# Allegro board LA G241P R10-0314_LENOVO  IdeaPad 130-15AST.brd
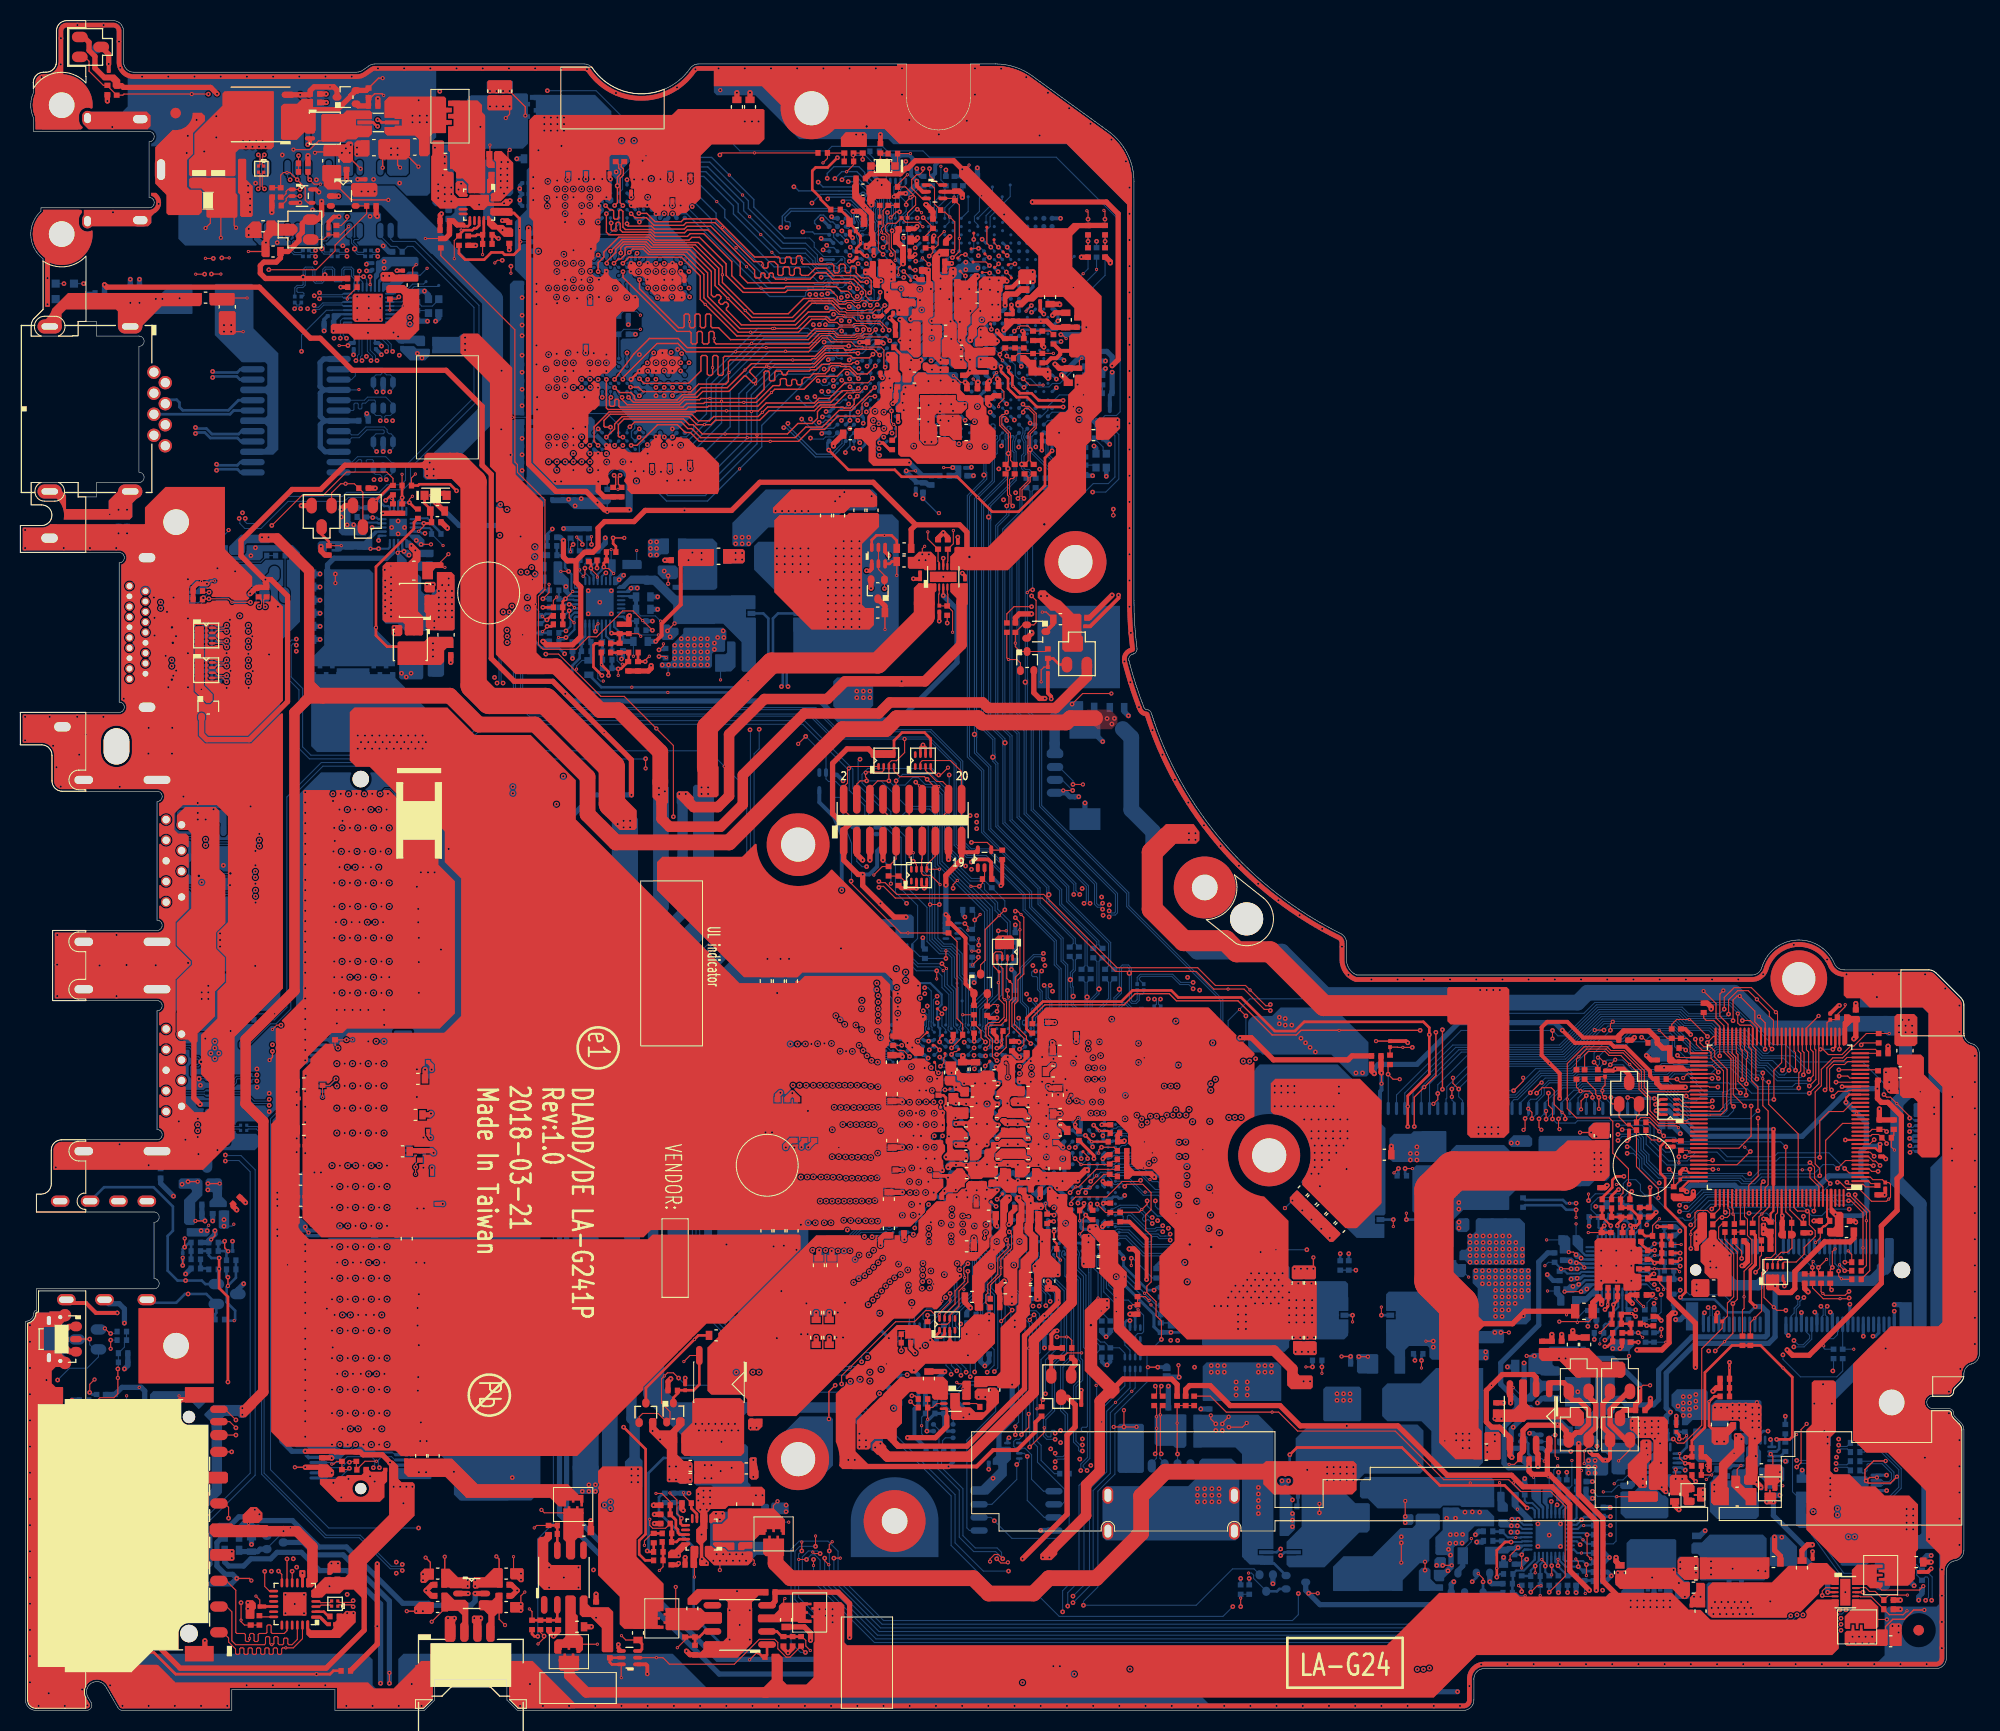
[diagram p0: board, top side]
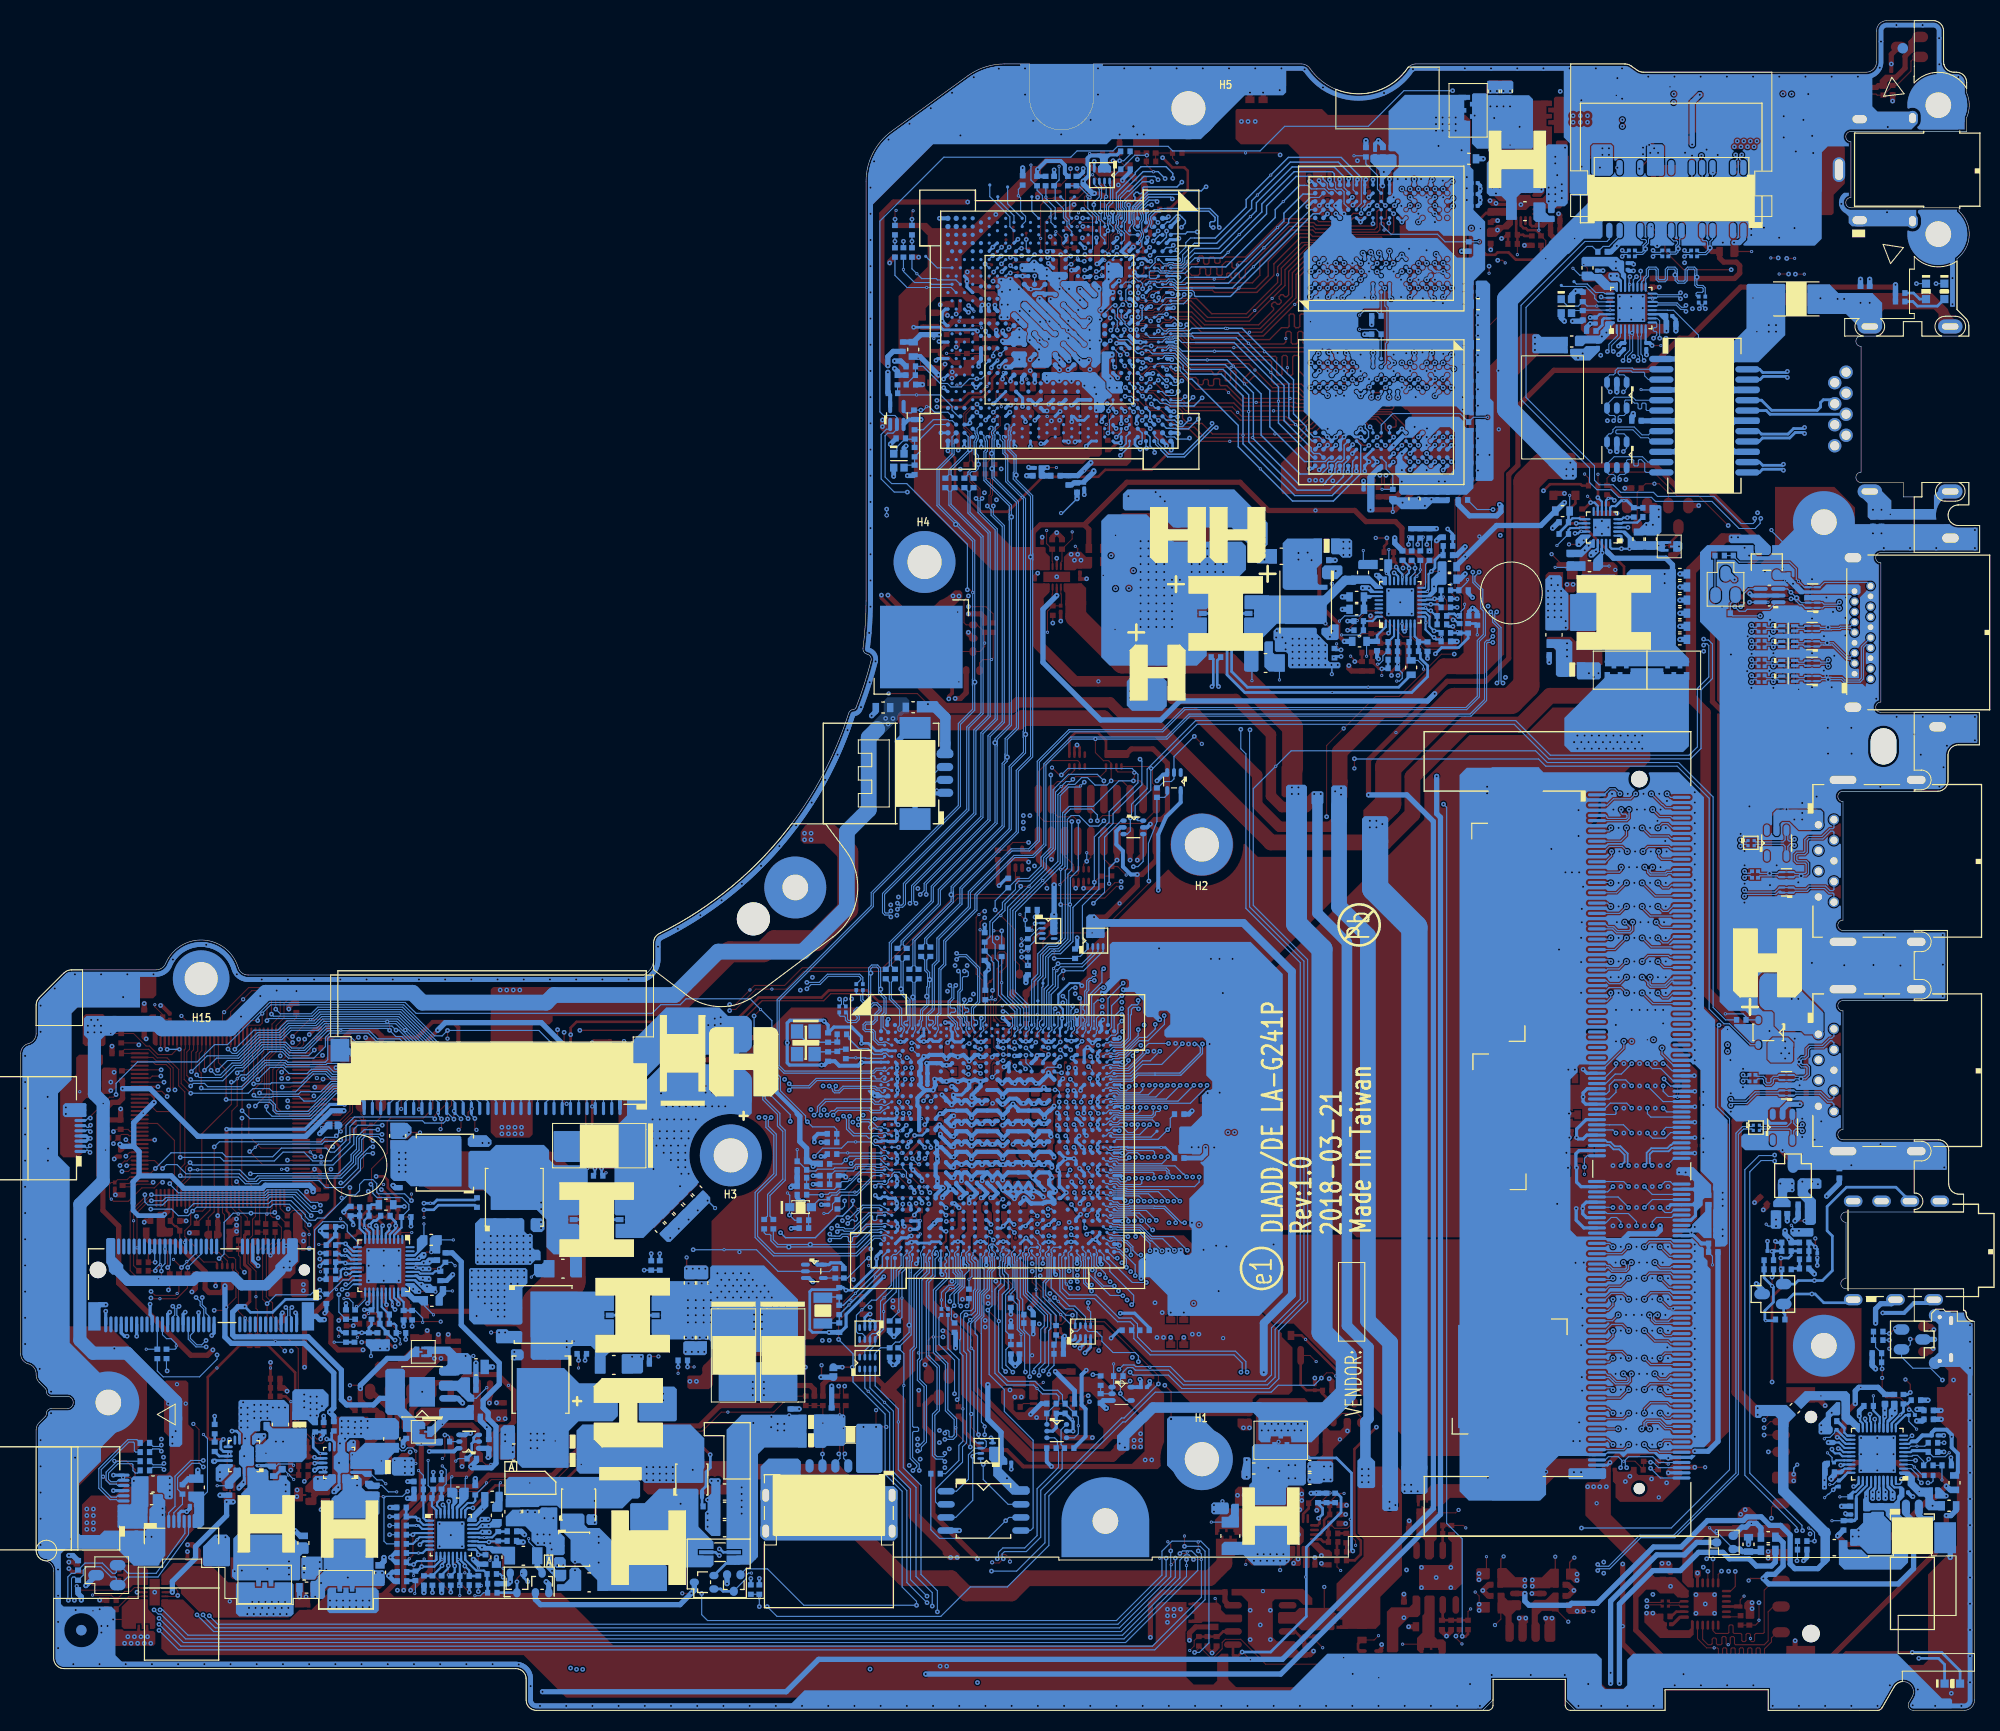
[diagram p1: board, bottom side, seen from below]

Outline 189.87 x 163.86 mm; copper layers: TOP, VCC, IN1, IN2, GND, BOTTOM. Coordinates in mm from the lower left corner of the outline.

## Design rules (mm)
net group 12: nets EXT_MIC_RING2 EXT_MIC_SLEEVE
net group 15: nets DMIC_CLK DMIC_CLK_R
net group CLK_PCIE_LAN: nets CLK_PCIE_LAN CLK_PCIE_LAN#
net group CLK_PCIE_WLAN: nets CLK_PCIE_WLAN CLK_PCIE_WLAN#
net group CLK_PEG_VGA: nets CLK_PEG_VGA CLK_PEG_VGA#
net group CLKREQ: nets VGA_CLKREQ# WLAN_CLKREQ#_R
net group DDR_A_CLK0: nets DDR_A_CLK0 DDR_A_CLK0#
net group DDR_A_CLK1: nets DDR_A_CLK1 DDR_A_CLK1#
net group DDR_A_SDQS0: nets DDR_A_SDQS0 DDR_A_SDQS0#
net group DDR_A_SDQS3: nets DDR_A_SDQS3 DDR_A_SDQS3#
net group DDR_A_SDQS4: nets DDR_A_SDQS4 DDR_A_SDQS4#
net group DDR_A_SDQS5: nets DDR_A_SDQS5 DDR_A_SDQS5#
net group DDR_A_SDQS6: nets DDR_A_SDQS6 DDR_A_SDQS6#
net group DDR_A_SDQS7: nets DDR_A_SDQS7 DDR_A_SDQS7#
net group DDRA_MISC: nets DDR_A_EVENT# DDR_A_RST#
net group EC_SMB_DA1: nets EC_SMB_CK1 EC_SMB_DA1
net group EC_SMB_DA2: nets EC_SMB_CK2 EC_SMB_DA2
net group EC_SMDA: nets EC_SMCA EC_SMDA
net group EDP_AUX: nets EDP_AUXN EDP_AUXP
net group EDP_AUX_C: nets EDP_AUXN_C EDP_AUXP_C
net group EDP_TX0: nets EDP_TXN0 EDP_TXP0
net group EDP_TX0_C: nets EDP_TXN0_C EDP_TXP0_C
net group EDP_TX1: nets EDP_TXN1 EDP_TXP1
net group EDP_TX1_C: nets EDP_TXN1_C EDP_TXP1_C
net group M_CLK0: nets M_CLK0 M_CLK#0
net group M_CLK1: nets M_CLK1 M_CLK#1
net group M_WCKA0_0: nets M_WCKA0_0 M_WCKA0_0#
net group M_WCKA0_1: nets M_WCKA0_1 M_WCKA0_1#
net group M_WCKA1_0: nets M_WCKA1_0 M_WCKA1_0#
net group M_WCKA1_1: nets M_WCKA1_1 M_WCKA1_1#
net group PCIE_ARX_C_GTX_0: nets PCIE_ARX_C_GTX_N0 PCIE_ARX_C_GTX_P0
net group PCIE_ARX_C_GTX_1: nets PCIE_ARX_C_GTX_N1 PCIE_ARX_C_GTX_P1
net group PCIE_ARX_C_GTX_2: nets PCIE_ARX_C_GTX_N2 PCIE_ARX_C_GTX_P2
net group PCIE_ARX_C_GTX_3: nets PCIE_ARX_C_GTX_N3 PCIE_ARX_C_GTX_P3
net group PCIE_ARX_GTX_0: nets PCIE_ARX_GTX_N0 PCIE_ARX_GTX_P0
net group PCIE_ARX_GTX_1: nets PCIE_ARX_GTX_N1 PCIE_ARX_GTX_P1
net group PCIE_ARX_GTX_2: nets PCIE_ARX_GTX_N2 PCIE_ARX_GTX_P2
net group PCIE_ARX_GTX_3: nets PCIE_ARX_GTX_N3 PCIE_ARX_GTX_P3
net group PCIE_ATX_C_GRX_0: nets PCIE_ATX_C_GRX_N0 PCIE_ATX_C_GRX_P0
net group PCIE_ATX_C_GRX_1: nets PCIE_ATX_C_GRX_N1 PCIE_ATX_C_GRX_P1
net group PCIE_ATX_C_GRX_2: nets PCIE_ATX_C_GRX_N2 PCIE_ATX_C_GRX_P2
net group PCIE_ATX_C_GRX_3: nets PCIE_ATX_C_GRX_N3 PCIE_ATX_C_GRX_P3
net group PCIE_ATX_GRX_0: nets PCIE_ATX_GRX_N0 PCIE_ATX_GRX_P0
net group PCIE_ATX_GRX_1: nets PCIE_ATX_GRX_N1 PCIE_ATX_GRX_P1
net group PCIE_ATX_GRX_2: nets PCIE_ATX_GRX_N2 PCIE_ATX_GRX_P2
net group PCIE_ATX_GRX_3: nets PCIE_ATX_GRX_N3 PCIE_ATX_GRX_P3
net group RJ45_RX1: nets RJ45_RX1+ RJ45_RX1-
net group RJ45_TX0: nets RJ45_TX0+ RJ45_TX0-
net group RJ45_TX2: nets RJ45_TX2+ RJ45_TX2-
net group RJ45_TX3: nets RJ45_TX3+ RJ45_TX3-
net group SATA_ARX_C_DTX_0: nets SATA_ARX_C_DTX_N0 SATA_ARX_C_DTX_P0
net group SATA_ARX_DTX_0: nets SATA_ARX_DTX_N0 SATA_ARX_DTX_P0
net group SATA_ARX_DTX_1: nets SATA_ARX_DTX_N1 SATA_ARX_DTX_P1
net group SATA_ATX_C_DRX_0: nets SATA_ATX_C_DRX_N0 SATA_ATX_C_DRX_P0
net group SATA_ATX_DRX_0: nets SATA_ATX_DRX_N0 SATA_ATX_DRX_P0
net group SATA_ATX_DRX_1: nets SATA_ATX_DRX_N1 SATA_ATX_DRX_P1
net group SENSE: nets VCCSENSE_VGA VSSSENSE_VGA
net group USB3_ATX_DRX_1: nets USB3_ATX_DRX_N1 USB3_ATX_DRX_P1
net group USB20_5_R: nets USB20_N5_R USB20_P5_R
net group USB20_6_R: nets USB20_N6_R USB20_P6_R
net group USB20_P1: nets USB20_N1 USB20_P1
net group 10: nets EC_SCI# H_PROCHOT# I2C0_SCL LAN_CLKREQ# PROCHOT# PXS_RST# SUSP SUSP# WLAN_CLKREQ#
net group 28: nets 32K_X1 32K_X2 48M_X1 48M_X1_R 48M_X2 48M_X2_R
net group AUDIO: nets HP_OUTL HP_OUTR HPOUT_L HPOUT_L1 HPOUT_R HPOUT_R1 LINE1-L LINE1-R
net group CLOCK: nets RTC_CLK
net group CPU-SV: nets APU_SVT SVC_RT3661 SVD_RT3661
net group DDRA_CMD: nets DDR_A_CKE0 DDR_A_CKE1 DDR_A_ODT0 DDR_A_ODT1 DDR_A_SACT# DDR_A_SBG0 DDR_A_SBG1 DDR_A_SBS0# DDR_A_SBS1# DDR_A_SCAS# DDR_A_SCS0# DDR_A_SCS1# DDR_A_SMA0 DDR_A_SMA1 DDR_A_SMA2 DDR_A_SMA3 DDR_A_SMA4 DDR_A_SMA5 DDR_A_SMA6 DDR_A_SMA7 DDR_A_SMA8 DDR_A_SMA9 DDR_A_SMA10 DDR_A_SMA11 DDR_A_SMA12 DDR_A_SMA13 DDR_A_SRAS# DDR_A_SWE#
net group DDRA_D0: nets DDR_A_SDM0 DDR_A_SDQ0 DDR_A_SDQ1 DDR_A_SDQ2 DDR_A_SDQ3 DDR_A_SDQ4 DDR_A_SDQ5 DDR_A_SDQ6 DDR_A_SDQ7
net group DDRA_D1: nets DDR_A_SDM1 DDR_A_SDQ8 DDR_A_SDQ9 DDR_A_SDQ10 DDR_A_SDQ11 DDR_A_SDQ12 DDR_A_SDQ13 DDR_A_SDQ14 DDR_A_SDQ15
net group DDRA_D2: nets DDR_A_SDM2 DDR_A_SDQ16 DDR_A_SDQ17 DDR_A_SDQ18 DDR_A_SDQ19 DDR_A_SDQ20 DDR_A_SDQ21 DDR_A_SDQ22 DDR_A_SDQ23
net group DDRA_D3: nets DDR_A_SDM3 DDR_A_SDQ24 DDR_A_SDQ25 DDR_A_SDQ26 DDR_A_SDQ27 DDR_A_SDQ28 DDR_A_SDQ29 DDR_A_SDQ30 DDR_A_SDQ31
net group DDRA_D4: nets DDR_A_SDM4 DDR_A_SDQ32 DDR_A_SDQ33 DDR_A_SDQ34 DDR_A_SDQ35 DDR_A_SDQ36 DDR_A_SDQ37 DDR_A_SDQ38 DDR_A_SDQ39
net group DDRA_D5: nets DDR_A_SDM5 DDR_A_SDQ40 DDR_A_SDQ41 DDR_A_SDQ42 DDR_A_SDQ43 DDR_A_SDQ44 DDR_A_SDQ45 DDR_A_SDQ46 DDR_A_SDQ47
net group DDRA_D6: nets DDR_A_SDM6 DDR_A_SDQ48 DDR_A_SDQ49 DDR_A_SDQ50 DDR_A_SDQ51 DDR_A_SDQ52 DDR_A_SDQ53 DDR_A_SDQ54 DDR_A_SDQ55
net group DDRA_D7: nets DDR_A_SDM7 DDR_A_SDQ56 DDR_A_SDQ57 DDR_A_SDQ58 DDR_A_SDQ59 DDR_A_SDQ60 DDR_A_SDQ61 DDR_A_SDQ62 DDR_A_SDQ63
net group DDRA_DQS: nets DDR_A_SDQS1 DDR_A_SDQS1# DDR_A_SDQS2 DDR_A_SDQS2#
net group DMIC: nets DMIC_DAT
net group GPU-SV: nets GPU_SVC GPU_SVD GPU_SVT
net group HDA: nets HDA_BITCLK HDA_BITCLK_AUDIO HDA_SDIN0 HDA_SDIN0_AUDIO HDA_SDIN1 HDA_SDIN2 HDA_SDOUT HDA_SDOUT_AUDIO HDA_SYNC HDA_SYNC_AUDIO
net group HDMI: nets APU_DP1_AUXN APU_DP1_AUXP APU_DP1_N0 APU_DP1_N1 APU_DP1_N2 APU_DP1_N3 APU_DP1_P0 APU_DP1_P1 APU_DP1_P2 APU_DP1_P3 HDMI_CLKN HDMI_CLKP HDMI_CTRL_CLK HDMI_CTRL_DAT HDMI_L_CLKN HDMI_L_CLKP HDMI_L_TX_N0 HDMI_L_TX_N1 HDMI_L_TX_N2 HDMI_L_TX_P0 HDMI_L_TX_P1 HDMI_L_TX_P2 HDMI_TX_N0 HDMI_TX_N1 HDMI_TX_N2 HDMI_TX_P0 HDMI_TX_P1 HDMI_TX_P2
net group I2C: nets APU_SCLK0 APU_SDATA0 I2C0_SCL_TP I2C0_SDA_TP
net group I2C0_SCL: nets I2C0_SDA
net group KB: nets KSI0 KSI1 KSI2 KSI3 KSI4 KSI5 KSI6 KSI7 KSO0 KSO1 KSO2 KSO3 KSO4 KSO5 KSO6 KSO7 KSO8 KSO9 KSO10 KSO11 KSO12 KSO13 KSO14 KSO15 KSO16 KSO16_R KSO17 KSO17_R
net group LAN: nets LAN_MDIN0 LAN_MDIN1 LAN_MDIN2 LAN_MDIN3 LAN_MDIP0 LAN_MDIP1 LAN_MDIP2 LAN_MDIP3
net group LPC: nets LPC_AD0 LPC_AD1 LPC_AD2 LPC_AD3 LPC_CLK0_EC LPC_CLK1 LPC_CLKRUN# LPC_FRAME# LPC_RST# LPC_RST#_R
net group PCIE-LAN: nets PCIE_ARX_C_DTX_N0 PCIE_ARX_C_DTX_P0 PCIE_ARX_DTX_N0 PCIE_ARX_DTX_P0 PCIE_ATX_C_DRX_N0 PCIE_ATX_C_DRX_P0 PCIE_ATX_DRX_N0 PCIE_ATX_DRX_P0
net group PCIE-WLAN: nets PCIE_ARX_DTX_N2 PCIE_ARX_DTX_P2 PCIE_ATX_C_DRX_N2 PCIE_ATX_C_DRX_P2 PCIE_ATX_DRX_N2 PCIE_ATX_DRX_P2
net group SD: nets SD_CD_N SD_CLK SD_CLK_R SD_CMD SD_D0 SD_D1 SD_D2 SD_D3 SD_WP
net group SMB: nets APU_SIC APU_SID VGA_SMB_CK3 VGA_SMB_DA3
net group SPI: nets APU_SPI_CLK APU_SPI_CLK_R APU_SPI_CS1# APU_SPI_CS2# APU_SPI_HOLD# APU_SPI_MISO APU_SPI_MOSI APU_SPI_WP#
net group SPK: nets SPK_L1- SPK_L1-_CONN SPK_L2+ SPK_L2+_CONN SPK_R1- SPK_R1-_CONN SPK_R2+ SPK_R2+_CONN
net group USB2.0: nets USB20_CR_N3 USB20_CR_P3 USB20_N2 USB20_N2_L USB20_N2_R USB20_N3 USB20_N5 USB20_N6 USB20_P2 USB20_P2_L USB20_P2_R USB20_P3 USB20_P5 USB20_P6
net group USB3.0: nets USB3_ARX_DTX_N1 USB3_ARX_DTX_N2 USB3_ARX_DTX_P1 USB3_ARX_DTX_P2 USB3_ATX_C_DRX_N1 USB3_ATX_C_DRX_N2 USB3_ATX_C_DRX_P1 USB3_ATX_C_DRX_P2 USB3_ATX_DRX_N2 USB3_ATX_DRX_P2
net group VRAM_ADD: nets M0_MA0 M0_MA1 M0_MA2 M0_MA3 M0_MA4 M0_MA5 M0_MA6 M0_MA7 M0_MA8 M1_MA0 M1_MA1 M1_MA2 M1_MA3 M1_MA4 M1_MA5 M1_MA6 M1_MA7 M1_MA8 M_ADBI0 M_ADBI1
net group VRAM_CTL: nets M_CAS#0 M_CAS#1 M_CKE0 M_CKE1 M_CS0B#0 M_CS1B#0 M_RAS#0 M_RAS#1 M_WE#0 M_WE#1
net group VRAM_D0: nets M_DA0 M_DA1 M_DA2 M_DA3 M_DA4 M_DA5 M_DA6 M_DA7 M_DBI0#
net group VRAM_D1: nets M_DA8 M_DA9 M_DA10 M_DA11 M_DA12 M_DA13 M_DA14 M_DA15 M_DBI1#
net group VRAM_D2: nets M_DA16 M_DA17 M_DA18 M_DA19 M_DA20 M_DA21 M_DA22 M_DA23 M_DBI2#
net group VRAM_D3: nets M_DA24 M_DA25 M_DA26 M_DA27 M_DA28 M_DA29 M_DA30 M_DA31 M_DBI3#
net group VRAM_D4: nets M_DA32 M_DA33 M_DA34 M_DA35 M_DA36 M_DA37 M_DA38 M_DA39 M_DBI4#
net group VRAM_D5: nets M_DA40 M_DA41 M_DA42 M_DA43 M_DA44 M_DA45 M_DA46 M_DA47 M_DBI5#
net group VRAM_D6: nets M_DA48 M_DA49 M_DA50 M_DA51 M_DA52 M_DA53 M_DA54 M_DA55 M_DBI6#
net group VRAM_D7: nets M_DA56 M_DA57 M_DA58 M_DA59 M_DA60 M_DA61 M_DA62 M_DA63 M_DBI7#
net group VRAM_EDC: nets M_EDC_0 M_EDC_1 M_EDC_2 M_EDC_3 M_EDC_4 M_EDC_5 M_EDC_6 M_EDC_7
nets with their own width: min track width 0.254; nets +EC_VCCA ECAGND
nets with their own width: min track width 0.381; nets +RTC_BATT +RTCBATT_R
nets with their own width: min track width 0.508; nets +0.6VS +0.95VALW +0.95VS +1.2V +1.8VALW +1.8VGS +1.8VS +1.35VS_VRAM +3VALW +3VALW_EC +3VGS +3VL +3VS +3VS_CMOS +5VALW +5VS +19V_P1 +CHGRTC_R +FBA_VREFC0 +RTCBATT +VDDR3 +VGA_CORE +VL ASGATE_CHG_R GND GNDA N17215363 N22801431
nets with their own width: min track width 1.016; nets +3V_LAN +3VS_WLAN +CARD_3V3 HGNDA HGNDB
nets with their own width: min track width 1.524; nets +LCDVDD +LCDVDD_CONN
nets with their own width: min track width 2.032; nets +5V_HDD +5V_ODD
nets with their own width: min track width 2.54; nets +LEDVDD

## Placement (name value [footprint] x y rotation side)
C179  100P_0402_50V8J  [C_0402]  169.64 47.35 270 top
C180  0.1U_0201_10V6K  [C_0201]  160.94 50.49 270 top
C181  0.1U_0201_10V6K  [C_0201]  180.24 54.3 270 top
C182  1000P_0402_50V7K  [C_0402]  177.89 67.01 90 top
C183  1000P_0402_50V7K  [C_0402]  176.35 47.46 0 top
C184  0.1U_0201_10V6K  [C_0201]  160.75 62.93 270 top
C187  0.1U_0201_10V6K  [C_0201]  175.41 67.57 270 top
C189  100P_0402_50V8J  [C_0402]  163.15 67.67 90 top
C190  100P_0402_50V8J  [C_0402]  168.75 45.57 0 top
C191  47P_0402_50V8J  [C_0402]  166.14 45.51 0 top
C193  0.1U_0201_10V6K  [C_0201]  160.87 51.49 90 top
C201  4.7U_0402_6.3V6M  [C_0402]  31.59 150.35 270 top
C202  0.1U_0201_10V K X5R  [C_0201]  23.75 142.97 180 top
C203  10U_0603_6.3V6M  [C_0603]  24.22 143.92 180 top
C204  0.1U_0201_10V K X5R  [C_0201]  29.85 143.12 90 top
C205  4.7U_0805_25V6-K  [C_0805]  35.09 151.54 180 top
C206  0.1U_0201_10V K X5R  [C_0201]  27.94 141 180 bottom
C207  0.1U_0201_10V K X5R  [C_0201]  27.94 141.57 180 bottom
C208  0.1U_0201_10V K X5R  [C_0201]  30.74 141 180 bottom
C209  0.1U_0201_10V K X5R  [C_0201]  30.74 141.57 180 bottom
C210  0.1U_0201_10V K X5R  [C_0201]  33.98 141 180 bottom
C211  0.1U_0201_10V K X5R  [C_0201]  33.98 141.57 180 bottom
C216  10P_0402_50V8J  [C_0402]  36.07 141.44 0 bottom
C217  1U_0201_6.3V6M  [C_0201]  33.43 147.88 90 top
C232  0.1U_0201_10V K X5R  [C_0201]  177.8 18.64 180 bottom
C233  0.01U_0402_16V7K  [C_0402]  177.37 23.27 0 bottom
C234  0.01U_0402_16V7K  [C_0402]  177.37 24.16 0 bottom
C235  0.01U_0402_16V7K  [C_0402]  177.37 25.05 0 bottom
C236  0.01U_0402_16V7K  [C_0402]  177.37 25.94 0 bottom
C237  1000P_0402_50V7K  [C_0402]  177.84 19.4 180 bottom
C238  10U_0603_6.3V6M  [C_0603]  177.88 20.48 180 bottom
C239  0.1U_0201_10V K X5R  [C_0201]  178.65 17.85 270 bottom
C243  4.7U_0402_6.3V6M  [C_0402]  164.04 46.22 180 top
C244  0.1U_0201_10V K X5R  [C_0201]  163.06 44.81 180 top
C271  0.1U_0201_10V K X5R  [C_0201]  132.74 64.32 90 top
C272  0.1U_0201_10V K X5R  [C_0201]  155.91 56.8 270 top
C275  0.1U_0201_10V K X5R  [C_0201]  153.58 61.45 90 top
C280  0.1U_0201_10V K X5R  [C_0201]  172.89 19.84 0 bottom
C281  82P_0402_50V8G  [C_0402]  184.3 12.62 270 bottom
C282  82P_0402_50V8G  [C_0402]  184.3 13.61 90 bottom
C301  0.1U_0201_10V K X5R  [C_0201]  22.29 61 180 bottom
C302  0.1U_0201_10V K X5R  [C_0201]  22.29 61.63 180 bottom
C303  470P_0402_50V7K  [C_0402]  17.93 87.08 90 bottom
C304  220U_6.3V_M  [C_MP6VLPS220MC4R2]  20.54 69.68 270 bottom
C305  0.1U_0201_10V K X5R  [C_0201]  18.23 64.55 180 bottom
C371  10U_0603_6.3V6M  [C_0603]  106.97 97.25 180 bottom
C823  4.7U_0402_6.3V6M  [C_0402]  175.36 47.46 180 top
C831  22P_0402_50V8J  [C_0402]  181.57 56.34 90 top
C832  0.1U_0201_10V6K  [C_0201]  160.24 55.25 270 top
C833  100P_0402_50V8J  [C_0402]  180.18 56.34 90 top
C834  100P_0402_50V8J  [C_0402]  180.1 63.72 0 top
C835  100P_0402_50V8J  [C_0402]  164.04 47.13 180 top
C836  1000P_0402_50V7K  [C_0402]  179.99 50.91 270 top
C837  100P_0402_50V8J  [C_0402]  171.68 47.27 180 top
C838  100P_0402_50V8J  [C_0402]  172.81 46.31 90 top
C839  0.1U_0201_10V K X5R  [C_0201]  22.04 80.74 180 bottom
C840  0.1U_0201_10V K X5R  [C_0201]  22.04 81.37 180 bottom
C843  0.1U_0201_10V K X5R  [C_0201]  173.71 14.11 90 top
C844  10U_0603_6.3V6M  [C_0603]  172.67 13.12 90 top
C845  10U_0603_6.3V6M  [C_0603]  183.03 14.38 0 top
C846  0.1U_0201_10V K X5R  [C_0201]  183.44 13.43 0 top
C847  2200P_0402_25V7K  [C_0402]  180.61 10.7 0 top
C848  1000P_0402_50V7K  [C_0402]  180.61 9.81 0 top
C849  0.1U_0201_10V K X5R  [C_0201]  161.95 9.58 90 top
C850  10U_0603_6.3V6M  [C_0603]  162.84 8.92 90 top
C851  10U_0603_6.3V6M  [C_0603]  180.56 6.7 0 top
C852  0.1U_0201_10V K X5R  [C_0201]  180.77 7.59 0 top
C853  4.7U_0402_6.3V6M  [C_0402]  63.39 26.19 0 top
C854  4.7U_0402_6.3V6M  [C_0402]  71.59 28.02 90 top
C855  1U_0201_6.3V6M  [C_0201]  70.83 28.71 270 top
C856  4.7U_0603_6.3V6M  [C_0603]  88.04 31.46 90 top
C857  10U_0603_6.3V6M  [C_0603]  94.39 31.78 270 top
C858  1U_0201_6.3V6M  [C_0201]  93.44 31.56 270 top
C859  0.1U_0201_10V6K  [C_0201]  64.42 31.04 90 top
C860  330P_0402_50V7K  [C_0402]  92.98 29.43 0 top
C861  1U_0201_6.3V6M  [C_0201]  89.78 28.48 0 top
C2147  0.1U_0201_10V K X5R  [C_0201]  182.44 59.97 180 top
C2148  1000P_0402_50V7K  [C_0402]  182.67 60.74 180 top
C2149  10U_0603_6.3V6M  [C_0603]  182.91 61.88 180 top
C2150  100P_0402_50V8J  [C_0402]  89.49 29.75 0 bottom
C2151  100P_0402_50V8J  [C_0402]  88.62 29.75 180 bottom
C2152  0.1U_0201_10V K X5R  [C_0201]  8.54 158.39 90 top
C2153  10P_0402_50V8J  [C_0402]  8.41 157.59 270 top
C2154  0.1U_0201_10V6K  [C_0201]  180.75 51.19 270 top
C2155  0.1U_0201_10V K X5R  [C_0201]  164.35 37.72 0 top
CA1  4.7U_0402_6.3V6M  [C_0402]  9.55 18.94 90 bottom
CA40  4.7U_0402_6.3V6M  [C_0402]  14.96 23.08 180 bottom
CA43  100P_0402_50V8J  [C_0402]  9.48 34.64 0 bottom
CA44  1U_0201_6.3V6M  [C_0201]  4.7 20.79 180 bottom
CA45  1000P_0402_50V7K  [C_0402]  41.06 11.1 180 top
CA46  1U_0201_6.3V6M  [C_0201]  19.95 44.54 0 bottom
CA47  1000P_0402_50V7K  [C_0402]  46.43 12.18 0 top
CA48  0.1U_0201_10V K X5R  [C_0201]  4.62 26.66 180 bottom
CA49  0.1U_0201_10V K X5R  [C_0201]  7.5 21.14 180 bottom
CA50  470P_0402_50V7K  [C_0402]  18.62 49.09 270 bottom
CA51  2.2U_0402_6.3V6M  [C_0402]  4.04 25.06 0 bottom
CA52  22P_0402_50V8J  [C_0402]  3.62 23.76 180 bottom
CA53  0.1U_0201_10V K X5R  [C_0201]  10.85 19.51 270 bottom
CA54  1U_0201_6.3V6M  [C_0201]  15.71 44.33 270 bottom
CA55  0.1U_0201_10V K X5R  [C_0201]  13.13 28.92 0 bottom
CA56  220P_0402_50V7K  [C_0402]  19.95 42.77 0 bottom
CA57  1U_0201_6.3V6M  [C_0201]  13.62 21.71 90 bottom
CA58  1U_0201_6.3V6M  [C_0201]  13.13 29.68 0 bottom
CA59  220P_0402_50V7K  [C_0402]  16.53 42.85 0 bottom
CA60  1U_0201_6.3V6M  [C_0201]  12.41 18.41 90 bottom
CA61  2.2U_0402_6.3V6M  [C_0402]  14.74 28.05 180 bottom
CA62  0.1U_0201_10V K X5R  [C_0201]  4.7 21.43 180 bottom
CA63  2.2U_0402_6.3V6M  [C_0402]  10.27 29.52 0 bottom
CA64  2.2U_0402_6.3V6M  [C_0402]  12.51 19.79 90 bottom
CA65  470P_0402_50V7K  [C_0402]  16.65 49.05 0 bottom
CA66  4.7U_0402_6.3V6M  [C_0402]  12.16 16.24 270 bottom
CA67  1000P_0402_50V7K  [C_0402]  41.06 12.18 180 top
CA68  1U_0201_6.3V6M  [C_0201]  13.83 27.21 0 bottom
CA69  0.1U_0201_10V K X5R  [C_0201]  6.84 28.63 180 bottom
CA70  1U_0201_6.3V6M  [C_0201]  14.09 24.03 0 bottom
CA71  1000P_0402_50V7K  [C_0402]  46.43 11.1 0 top
CC1  0.1U_0201_10V6K  [C_0201]  109.88 67.68 90 bottom
CC2  0.1U_0201_10V6K  [C_0201]  110.52 67.68 90 bottom
CC3  0.1U_0201_10V6K  [C_0201]  108.23 69.84 90 bottom
CC4  0.1U_0201_10V6K  [C_0201]  108.87 69.84 90 bottom
CC7  0.01U_0402_16V7K  [C_0402]  85.09 80.9 270 top
CC8  0.1U_0201_10V6K  [C_0201]  111.57 49.04 90 bottom
CC9  150P_0402_50V8J  [C_0402]  85.18 30.71 270 bottom
CC10  0.1U_0201_10V6K  [C_0201]  81.28 31.34 180 bottom
CC11  12P_0402_50V8J  [C_0402]  110.52 37.57 270 bottom
CC12  12P_0402_50V8J  [C_0402]  110.52 40.09 90 bottom
CC13  150P_0402_50V8J  [C_0402]  89.7 35.46 180 bottom
CC14  0.1U_0201_10V6K  [C_0201]  94.43 24.03 180 bottom
CC15  6.8P_0402_50V8C  [C_0402]  111.6 64.79 90 bottom
CC16  6.8P_0402_50V8C  [C_0402]  111.6 63.86 270 bottom
CC18  0.22U_0402_6.3V6K  [C_0402]  100.98 34.19 0 top
CC19  1U_0201_6.3V6M  [C_0201]  102.22 29.62 0 top
CC20  22U_0603_6.3V6M  [C_0603]  84.46 62.14 90 top
CC21  22U_0603_6.3V6M  [C_0603]  84.46 60.49 270 top
CC22  22U_0603_6.3V6M  [C_0603]  84.48 55.97 270 top
CC23  22U_0603_6.3V6M  [C_0603]  84.17 48.86 90 top
CC24  22U_0603_6.3V6M  [C_0603]  84.17 47.46 270 top
CC25  22U_0603_6.3V6M  [C_0603]  72.29 47.21 270 top
CC26  22U_0603_6.3V6M  [C_0603]  73.56 47.21 270 top
CC27  22U_0603_6.3V6M  [C_0603]  74.83 47.21 270 top
CC28  22U_0603_6.3V6M  [C_0603]  72.23 70.01 90 top
CC29  22U_0603_6.3V6M  [C_0603]  73.5 70.01 90 top
CC30  22U_0603_6.3V6M  [C_0603]  74.77 70.01 90 top
CC31  0.22U_0402_6.3V6K  [C_0402]  87.06 62.89 90 top
CC32  0.22U_0402_6.3V6K  [C_0402]  75.28 58.31 90 top
CC33  0.22U_0402_6.3V6K  [C_0402]  75.02 56.18 270 top
CC34  0.22U_0402_6.3V6K  [C_0402]  75.97 56.18 270 top
CC35  0.22U_0402_6.3V6K  [C_0402]  73.37 58.31 90 top
CC36  0.22U_0402_6.3V6K  [C_0402]  74.32 58.31 90 top
CC37  180P_0402_50V8J  [C_0402]  76.93 56.18 270 top
CC38  0.22U_0402_6.3V6K  [C_0402]  88.97 60.57 270 top
CC39  0.22U_0402_6.3V6K  [C_0402]  89.16 54.76 0 top
CC40  0.22U_0402_6.3V6K  [C_0402]  88.75 52.82 270 top
CC41  0.22U_0402_6.3V6K  [C_0402]  89.17 50.97 0 top
CC42  180P_0402_50V8J  [C_0402]  84.8 53.32 270 top
CC43  180P_0402_50V8J  [C_0402]  85.63 47.22 270 top
CC44  10U_0603_6.3V6M  [C_0603]  92.93 40.1 180 top
CC45  22U_0603_6.3V6M  [C_0603]  97.18 41.94 0 top
CC46  10U_0603_6.3V6M  [C_0603]  97.18 40.67 0 top
CC47  0.22U_0402_6.3V6K  [C_0402]  97.68 46.77 0 top
CC48  1U_0201_6.3V6M  [C_0201]  97.97 48.23 0 top
CC49  1U_0201_6.3V6M  [C_0201]  97.97 47.59 0 top
CC50  1U_0201_6.3V6M  [C_0201]  96.92 50.46 180 top
CC51  10U_0603_6.3V6M  [C_0603]  96.17 40.92 180 top
CC52  0.22U_0402_6.3V6K  [C_0402]  96.88 47.78 180 top
CC53  10U_0603_6.3V6M  [C_0603]  99.72 40.92 90 top
CC54  0.22U_0402_6.3V6K  [C_0402]  98.85 50.51 180 top
CC55  10U_0603_6.3V6M  [C_0603]  105.18 43.4 180 top
CC56  10U_0603_6.3V6M  [C_0603]  105.18 44.61 180 top
CC57  0.22U_0402_6.3V6K  [C_0402]  105.63 46.31 90 top
CC58  10U_0603_6.3V6M  [C_0603]  78.39 36.86 270 top
CC59  10U_0603_6.3V6M  [C_0603]  77.12 36.86 270 top
CC60  10U_0603_6.3V6M  [C_0603]  78.39 39.27 270 top
CC61  1U_0201_6.3V6M  [C_0201]  89.92 49.69 180 top
CC62  10U_0603_6.3V6M  [C_0603]  78.64 42.45 90 top
CC63  0.22U_0402_6.3V6K  [C_0402]  91.71 49.05 0 top
CC64  10U_0603_6.3V6M  [C_0603]  77.12 39.27 270 top
CC65  10U_0603_6.3V6M  [C_0603]  77.37 42.45 90 top
CC66  10U_0603_6.3V6M  [C_0603]  91 45 0 top
CC67  10U_0603_6.3V6M  [C_0603]  93.12 47.97 0 top
CC68  0.22U_0402_6.3V6K  [C_0402]  92.15 51.03 180 top
CC69  180P_0402_50V8J  [C_0402]  93.17 51.06 0 top
CC70  10U_0603_6.3V6M  [C_0603]  100.9 46.23 180 top
CC71  0.22U_0402_6.3V6K  [C_0402]  101.16 49.75 90 top
CC72  0.22U_0402_6.3V6K  [C_0402]  99.6 65.8 90 top
CC73  0.22U_0402_6.3V6K  [C_0402]  101.42 65.5 0 top
CC74  0.22U_0402_6.3V6K  [C_0402]  96.1 63.96 90 top
CC75  0.22U_0402_6.3V6K  [C_0402]  105.63 57.7 270 top
CC76  0.22U_0402_6.3V6K  [C_0402]  95.46 48.73 0 top
CC104  0.22U_0402_6.3V6K  [C_0402]  106.01 70.95 90 bottom
CC105  0.22U_0402_6.3V6K  [C_0402]  105.12 70.95 90 bottom
CC106  0.22U_0402_6.3V6K  [C_0402]  104.87 72.98 90 bottom
CC107  0.22U_0402_6.3V6K  [C_0402]  103.98 72.98 90 bottom
CC108  0.22U_0402_6.3V6K  [C_0402]  103.72 70.95 90 bottom
CC109  0.22U_0402_6.3V6K  [C_0402]  102.83 70.95 90 bottom
CC110  0.22U_0402_6.3V6K  [C_0402]  102.58 73.11 90 bottom
CC111  0.22U_0402_6.3V6K  [C_0402]  101.69 73.11 90 bottom
CC112  100P_0402_50V8J  [C_0402]  84.58 65.39 270 top
CC113  100P_0402_50V8J  [C_0402]  87.66 73.83 270 bottom
CC114  100P_0402_50V8J  [C_0402]  96.42 72.73 90 bottom
CC115  100P_0402_50V8J  [C_0402]  90.4 65.51 0 top
CC129  4.7U_0402_6.3V6M  [C_0402]  143.03 29.82 270 top
CC130  4.7U_0402_6.3V6M  [C_0402]  157.46 29.11 180 top
CC131  4.7U_0402_6.3V6M  [C_0402]  147.47 35.79 270 top
CC132  22U_0603_6.3V6M  [C_0603]  151.67 34.76 90 top
CC133  22U_0603_6.3V6M  [C_0603]  150.46 34.76 90 top
CC134  4.7U_0402_6.3V6M  [C_0402]  149.38 35.79 270 top
CC135  4.7U_0402_6.3V6M  [C_0402]  148.43 35.79 270 top
CC162  100P_0402_50V8J  [C_0402]  114.59 50.83 180 bottom
CD201  0.1U_0201_10V6K  [C_0201]  35.36 23.33 0 top
CD202  2.2U_0402_6.3V6M  [C_0402]  35.26 22.51 0 top
CD203  10U_0603_6.3V6M  [C_0603]  40.03 23.97 90 top
CD204  10U_0603_6.3V6M  [C_0603]  38.83 23.97 90 top
CD205  1U_0201_6.3V6M  [C_0201]  37.94 24.25 90 top
CD206  0.1U_0201_10V6K  [C_0201]  37.37 24.25 90 top
CD207  4.7U_0402_6.3V6M  [C_0402]  29.21 23.58 90 top
CD208  0.1U_0201_10V6K  [C_0201]  29.21 22.8 270 top
CD210  0.1U_0201_10V6K  [C_0201]  25.61 45.99 0 bottom
CD211  1000P_0402_50V7K  [C_0402]  25.38 47.32 0 bottom
CD212  0.1U_0201_10V6K  [C_0201]  25.64 50.64 0 bottom
CD213  0.1U_0201_10V6K  [C_0201]  25.61 46.56 0 bottom
CD214  10U_0603_6.3V6M  [C_0603]  27.84 51.47 180 top
CD215  10U_0603_6.3V6M  [C_0603]  27.84 48.35 180 top
CD216  10U_0603_6.3V6M  [C_0603]  37.8 61.24 0 top
CD217  10U_0603_6.3V6M  [C_0603]  37.56 57.75 0 top
CD218  10U_0603_6.3V6M  [C_0603]  36.32 54.21 0 top
CD219  10U_0603_6.3V6M  [C_0603]  37.43 46.45 270 top
CD220  10U_0603_6.3V6M  [C_0603]  28.16 60.8 180 top
CD221  10U_0603_6.3V6M  [C_0603]  28.16 56.29 180 top
CD222  1U_0201_6.3V6M  [C_0201]  27.5 54.77 180 top
CD223  1U_0201_6.3V6M  [C_0201]  27.56 59.34 180 top
CD224  1U_0201_6.3V6M  [C_0201]  36.48 46.04 270 top
CD225  1U_0201_6.3V6M  [C_0201]  38.91 62.88 0 top
CD226  1U_0201_6.3V6M  [C_0201]  38.91 56.21 0 top
CD227  1U_0201_6.3V6M  [C_0201]  39.3 52.04 0 top
CD228  1U_0201_6.3V6M  [C_0201]  27.5 49.81 180 top
CD229  1U_0201_6.3V6M  [C_0201]  39.74 49.12 0 top
CD230  330U_D3_2.5VY_R6M  [C_D3]  38.62 89.5 270 top
CD231  100P_0402_50V8J  [C_0402]  30.48 65.03 90 top
CH11  0.1U_0201_10V K X5R  [C_0201]  18.51 110.16 90 bottom
CH12  0.1U_0201_10V K X5R  [C_0201]  21.58 112.74 0 bottom
CH13  0.1U_0201_10V K X5R  [C_0201]  21.4 104.61 180 bottom
CH14  0.1U_0201_10V K X5R  [C_0201]  21.4 105.25 180 bottom
CH15  0.1U_0201_10V K X5R  [C_0201]  21.4 99.73 180 bottom
CH16  0.1U_0201_10V K X5R  [C_0201]  21.4 100.36 180 bottom
CH17  0.1U_0201_10V K X5R  [C_0201]  21.4 103.09 180 bottom
CH18  0.1U_0201_10V K X5R  [C_0201]  21.4 103.73 180 bottom
CH19  0.1U_0201_10V K X5R  [C_0201]  21.4 101.25 180 bottom
CH20  0.1U_0201_10V K X5R  [C_0201]  21.4 101.88 180 bottom
CL1  1U_0201_6.3V6M  [C_0201]  39.49 131.79 0 bottom
CL2  0.1U_0201_10V K X5R  [C_0201]  30.36 135.22 180 bottom
CL3  0.1U_0201_10V K X5R  [C_0201]  36.98 132.72 270 bottom
CL4  0.1U_0201_10V K X5R  [C_0201]  34.43 132.59 270 bottom
CL5  0.1U_0201_10V K X5R  [C_0201]  32.29 132.59 270 bottom
CL6  0.1U_0201_10V K X5R  [C_0201]  34.67 139.71 180 bottom
CL7  0.1U_0201_10V K X5R  [C_0201]  37.18 135.07 270 bottom
CL8  1U_0201_6.3V6M  [C_0201]  34.67 140.34 180 bottom
CL10  0.1U_0201_10V K X5R  [C_0201]  37.09 139.03 90 top
CL11  0.1U_0201_10V K X5R  [C_0201]  27.21 137.1 270 bottom
CL12  0.1U_0201_10V K X5R  [C_0201]  26.57 137.1 270 bottom
CL13  27P_0402_50V8J  [C_0402]  38.45 137.52 270 bottom
CL14  27P_0402_50V8J  [C_0402]  38.45 134.83 90 bottom
CL15  0.1U_0201_10V K X5R  [C_0201]  37.09 139.03 90 bottom
CL18  0.01U_0402_16V7K  [C_0402]  33.7 125.06 180 bottom
CL19  1000P_0603_50V8J  [C_0603]  18.63 137 180 top
CL20  4.7U_0402_6.3V6M  [C_0402]  30.33 134.46 180 bottom
CL21  4.7U_0402_6.3V6M  [C_0402]  37.81 132.89 270 bottom
CLRP1  SHORT PADS  [SHORTPADS]  111.09 32.8 270 bottom
CR1  0.1U_0201_10V K X5R  [C_0201]  29.94 12.76 90 top
CR2  4.7U_0402_6.3V6M  [C_0402]  30.7 12.72 90 top
CR3  5P_0402_50V8C  [C_0402]  22.3 8.27 90 top
CR4  1U_0201_6.3V6M  [C_0201]  22.6 10.06 0 top
CR5  1U_0201_6.3V6M  [C_0201]  30.48 8.35 180 top
CR6  4.7U_0402_6.3V6M  [C_0402]  21.95 17.62 90 top
CR7  0.1U_0201_10V K X5R  [C_0201]  22.84 17.79 90 top
CV1  0.22U_0402_6.3V6K  [C_0402]  100.23 119.49 270 bottom
CV2  0.22U_0402_6.3V6K  [C_0402]  99.34 119.49 270 bottom
CV3  0.22U_0402_6.3V6K  [C_0402]  98.39 119.49 270 bottom
CV4  0.22U_0402_6.3V6K  [C_0402]  97.5 119.49 270 bottom
CV5  0.22U_0402_6.3V6K  [C_0402]  97.31 120.82 270 top
CV6  0.22U_0402_6.3V6K  [C_0402]  98.2 120.82 270 top
CV7  0.22U_0402_6.3V6K  [C_0402]  96.36 120.82 270 top
CV8  0.22U_0402_6.3V6K  [C_0402]  95.47 120.82 270 top
CV11  0.082U_0402_16V  [C_0402]  98.14 133.75 270 top
CV15  0.68U_0402_10V  [C_0402]  103.13 130.33 0 bottom
CV17  15P_0402_50V8J  [C_0402]  103.22 120.76 270 bottom
CV18  15P_0402_50V8J  [C_0402]  104.09 123.35 0 bottom
CV19  10U_0603_6.3V6M  [C_0603]  101.32 134.13 90 top
CV20  1U_0201_6.3V6M  [C_0201]  96.17 134.8 90 top
CV21  0.1U_0201_10V6K  [C_0201]  95.53 134.8 90 top
CV26  1U_0201_6.3V6M  [C_0201]  98.83 137.23 270 top
CV27  10U_0603_6.3V6M  [C_0603]  99.79 137.76 270 top
CV28  0.68U_0402_10V  [C_0402]  96.25 131.13 0 top
CV29  0.68U_0402_10V  [C_0402]  95.44 132.12 90 top
CV30  10U_0603_6.3V6M  [C_0603]  97.33 137.77 90 top
CV31  0.1U_0201_10V7K  [C_0201]  90.85 113.23 270 top
CV32  0.1U_0201_10V7K  [C_0201]  87.19 110.34 90 top
CV33  1U_0201_6.3V6M  [C_0201]  95.6 137.41 90 top
CV36  4.7U_0402_6.3V6M  [C_0402]  102.44 105.95 0 top
CV37  1U_0201_6.3V6M  [C_0201]  102.61 105.12 0 top
CV38  10U_0603_6.3V6M  [C_0603]  103.28 123.66 0 top
CV39  0.1U_0201_10V6K  [C_0201]  99.57 123.73 180 top
CV40  2.2U_0402_6.3V6M  [C_0402]  83.49 140.25 180 top
CV41  2.2U_0402_6.3V6M  [C_0402]  83.49 139.34 180 top
CV42  2.2U_0402_6.3V6M  [C_0402]  84.67 131.22 0 top
CV43  10U_0603_6.3V6M  [C_0603]  81.13 123.75 180 top
CV44  10U_0603_6.3V6M  [C_0603]  69.43 154.78 90 top
CV45  10U_0603_6.3V6M  [C_0603]  70.7 154.78 90 top
CV46  1U_0201_6.3V6M  [C_0201]  99.57 123.09 180 top
CV47  2.2U_0402_6.3V6M  [C_0402]  84.67 130.32 0 top
CV48  2.2U_0402_6.3V6M  [C_0402]  86.46 136.43 90 top
CV49  0.1U_0201_10V6K  [C_0201]  85.66 136.74 90 top
CV50  0.1U_0201_10V6K  [C_0201]  83.66 138.12 180 top
CV51  0.1U_0201_10V6K  [C_0201]  84.58 136.11 270 top
CV52  0.1U_0201_10V6K  [C_0201]  83.93 135.68 225 top
CV53  0.1U_0201_10V6K  [C_0201]  83.94 129.74 180 top
CV54  10U_0603_6.3V6M  [C_0603]  87.35 129.24 180 top
CV55  10U_0603_6.3V6M  [C_0603]  86.39 125.76 0 top
CV56  1U_0201_6.3V6M  [C_0201]  85.05 126.12 270 top
CV57  1U_0201_6.3V6M  [C_0201]  86.79 127.35 0 top
CV58  1U_0201_6.3V6M  [C_0201]  88.36 127.96 270 top
CV59  1U_0201_6.3V6M  [C_0201]  89.75 127.96 270 top
CV60  1U_0201_6.3V6M  [C_0201]  86.79 126.71 0 top
CV61  10U_0603_6.3V6M  [C_0603]  101.55 130.14 270 top
CV62  1U_0201_6.3V6M  [C_0201]  93.63 130.37 270 top
CV63  0.1U_0201_10V6K  [C_0201]  92.99 130.37 270 top
CV64  1U_0201_6.3V6M  [C_0201]  93.5 132.53 270 top
CV65  1U_0201_6.3V6M  [C_0201]  94.13 132.53 270 top
CV66  1U_0201_6.3V6M  [C_0201]  92.86 132.53 270 top
CV80  1U_0201_6.3V6M  [C_0201]  89.7 130.1 90 top
CV81  10U_0603_6.3V6M  [C_0603]  84.89 142.59 0 top
CV82  1U_0201_6.3V6M  [C_0201]  85.59 141.57 0 top
CV83  0.1U_0201_10V7K  [C_0201]  99.57 101.17 270 top
CV84  10U_0603_6.3V6M  [C_0603]  80.93 147.48 0 top
CV85  1U_0201_6.3V6M  [C_0201]  81.65 146.52 0 top
CV86  0.1U_0201_10V6K  [C_0201]  82.68 142.21 270 top
CV90  0.1U_0201_10V K X5R  [C_0201]  88.42 142.44 270 top
CV91  10U_0603_6.3V6M  [C_0603]  80.36 144.3 0 top
CV92  1U_0201_6.3V6M  [C_0201]  80.97 143.41 180 top
CV93  0.1U_0201_10V6K  [C_0201]  81.02 141.45 270 top
CV94  1U_0201_6.3V6M  [C_0201]  90.99 120.49 0 bottom
CV95  1U_0201_6.3V6M  [C_0201]  86.77 119.07 270 bottom
CV96  120P_0402_50V8J  [C_0402]  79.85 151.02 90 top
CV97  68P_0402_50V8J  [C_0402]  81.63 151.02 90 top
CV98  0.1U_0201_10V K X5R  [C_0201]  83.28 144.85 270 top
CV99  0.1U_0201_10V K X5R  [C_0201]  85.97 144.72 180 top
CV120  1U_0201_6.3V6M  [C_0201]  89.05 127.96 270 top
CV121  1U_0201_6.3V6M  [C_0201]  90.45 127.96 270 top
CV122  10U_0603_6.3V6M  [C_0603]  89.69 124.05 180 top
CV123  10U_0603_6.3V6M  [C_0603]  103.34 132.68 270 bottom
CV124  0.1U_0201_10V6K  [C_0201]  85.59 140.94 0 top
CV160  10U_0603_6.3V6M  [C_0603]  54.76 118.2 270 bottom
CV161  1U_0201_6.3V6M  [C_0201]  49.22 127.35 180 bottom
CV162  1U_0201_6.3V6M  [C_0201]  49.22 121 180 bottom
CV163  1U_0201_6.3V6M  [C_0201]  52.54 118.05 270 bottom
CV164  1U_0201_6.3V6M  [C_0201]  60.63 120.68 0 top
CV165  0.1U_0201_10V K X5R  [C_0201]  49.22 125.76 180 bottom
CV166  0.1U_0201_10V K X5R  [C_0201]  49.22 119.41 180 bottom
CV167  0.1U_0201_10V K X5R  [C_0201]  51.53 118.05 270 bottom
CV168  10U_0603_6.3V6M  [C_0603]  49.3 136.36 180 bottom
CV169  1U_0201_6.3V6M  [C_0201]  52.5 149 0 top
CV170  1U_0201_6.3V6M  [C_0201]  56.5 149.06 0 top
CV171  1U_0201_6.3V6M  [C_0201]  62.41 149 0 top
CV172  1U_0201_6.3V6M  [C_0201]  49.22 137.57 180 bottom
CV173  0.1U_0201_10V K X5R  [C_0201]  59.76 147.29 180 top
CV174  0.01U_0402_16V7K  [C_0402]  85.77 135.57 0 top
CV175  0.01U_0402_16V7K  [C_0402]  83.95 127.47 0 top
CV176  0.01U_0402_16V7K  [C_0402]  84.99 129.25 270 top
CV177  0.01U_0402_16V7K  [C_0402]  83.04 132.68 180 top
CV178  0.01U_0402_16V7K  [C_0402]  84.71 137.27 90 top
CV179  0.01U_0402_16V7K  [C_0402]  103.52 124.74 0 top
CV181  1U_0201_6.3V6M  [C_0201]  87.63 130.33 180 top
CV187  0.1U_0201_10V K X5R  [C_0201]  49.22 148.11 180 bottom
CV188  0.1U_0201_10V K X5R  [C_0201]  64.35 148.84 0 top
CV271  2200P_0402_50V7K  [C_0402]  89.88 112.6 90 top
CV281  2200P_0402_50V7K  [C_0402]  88.93 112.6 90 top
CV291  1U_0201_6.3V6M  [C_0201]  87.18 109.11 90 top
CV301  1U_0201_6.3V6M  [C_0201]  91.54 109.09 90 top
CV373  10U_0603_6.3V6M  [C_0603]  49.3 132.43 180 bottom
CV374  0.1U_0201_10V K X5R  [C_0201]  49.22 130.52 180 bottom
CV375  0.1U_0201_10V K X5R  [C_0201]  49.22 128.94 180 bottom
CV376  0.1U_0201_10V K X5R  [C_0201]  49.22 124.17 180 bottom
CV377  0.1U_0201_10V K X5R  [C_0201]  49.22 122.59 180 bottom
CV378  0.1U_0201_10V K X5R  [C_0201]  53.69 118.05 270 bottom
CV379  0.1U_0201_10V K X5R  [C_0201]  64.32 121 0 top
CV380  0.1U_0201_10V K X5R  [C_0201]  62.35 120.68 0 top
CV381  10U_0603_6.3V6M  [C_0603]  50.19 150.46 180 bottom
CV382  0.1U_0201_10V K X5R  [C_0201]  62.6 146.46 0 top
CV383  0.1U_0201_10V K X5R  [C_0201]  54.22 149.06 0 top
CV384  0.1U_0201_10V K X5R  [C_0201]  49.22 138.4 180 bottom
CV385  0.1U_0201_10V K X5R  [C_0201]  63.76 138.61 0 top
CV386  0.1U_0201_10V K X5R  [C_0201]  49.22 147.03 180 bottom
CV387  0.1U_0201_10V K X5R  [C_0201]  49.22 145.89 180 bottom
CV388  0.1U_0201_10V K X5R  [C_0201]  54.63 136.49 0 top
CV389  1U_0201_6.3V6M  [C_0201]  55.37 132.24 180 top
CV391  1U_0201_6.3V6M  [C_0201]  58.57 150.74 90 bottom
CV392  1U_0201_6.3V6M  [C_0201]  59.11 118.39 0 bottom
CV1380  0.1U_0201_10V K X5R  [C_0201]  89.05 107.13 270 top
D1  -  [L03ESDL5V0CC3-2_SOT23-3]  5.46 35.97 90 bottom
D281  -  [PSOT24C_SOT23-3]  182.55 13.11 270 bottom
D301  L05ESDL5V0NA-4 SLP2510P8 ESD  [YSCLAMP0524P_SLP2510P8-10-9]  18.26 59.62 90 bottom
D302  L30ESDL5V0C6-4 SOT23 ESD  [AZC099-04SPR7G_SOT23-6]  20.03 55.3 180 bottom
D303  L03ESDL5V0CC3-2  [L03ESDL5V0CC3-2_SOT23-3]  155.92 60.89 180 top
D304  L05ESDL5V0NA-4 SLP2510P8 ESD  [YSCLAMP0524P_SLP2510P8-10-9]  18.26 79.29 90 bottom
D305  L30ESDL5V0C6-4 SOT23 ESD  [AZC099-04SPR7G_SOT23-6]  20.6 82.85 180 bottom
DA3  AZC099-04S.R7G_SOT23-6  [AZC099-04SPR7G_SOT23-6]  42.47 12.28 270 top
DA8  -  [L03ESDL5V0CC3-2_SOT23-3]  21.05 40.37 270 bottom
DA9  -  [L03ESDL5V0CC3-2_SOT23-3]  18.06 52.89 0 bottom
DC3  RB751V-40 SOD-323  [RB751V-40TE17_SOD323-2]  115.31 48.8 90 bottom
DH1  L05ESDL5V0NA-4 SLP2510P8 ESD  [YSCLAMP0524P_SLP2510P8-10-9]  15.72 106.92 90 bottom
DH2  L05ESDL5V0NA-4 SLP2510P8 ESD  [YSCLAMP0524P_SLP2510P8-10-9]  15.78 103.17 90 bottom
DH3  L05ESDL5V0NA-4 SLP2510P8 ESD  [YSCLAMP0524P_SLP2510P8-10-9]  15.78 99.8 90 bottom
DL1  AZC099-04S.R7G_SOT23-6  [AZC099-04SPR7G_SOT23-6]  34.19 128.79 0 bottom
DL2  AZC099-04S.R7G_SOT23-6  [AZC099-04SPR7G_SOT23-6]  34.19 123.01 0 bottom
DL3  -  [BS4200N-C-LV_SMB-F2]  15.53 136.87 0 bottom
DV1  RB751V_SOD323  [CH751H-40PT_SOD323-2]  84.76 149.76 180 top
FD1  CF  [FIDUCIAL_C40M80]  183.99 7.78 0 top
FD2  CF  [FIDUCIAL_C40M80]  15.03 154.89 0 top
FD3  CF  [FIDUCIAL_C40M80]  7.42 161.18 180 bottom
FD4  CF  [FIDUCIAL_C40M80]  183.99 7.78 180 bottom
H1  HOLEA  [H_3P3]  75.37 24.36 270 top
H2  HOLEA  [H_3P3]  75.37 83.96 270 top
H3  HOLEA  [H_3P3]  121.03 53.82 270 top
H4  HOLEA  [H_3P3]  102.25 111.36 270 top
H5  HOLEA  [H_3P3]  76.67 155.36 270 top
H6  HOLEA  [H_2P5]  3.98 155.66 270 top
H7  HOLEA  [H_2P5]  3.98 143.16 270 top
H8  HOLEA  [H_2P5]  15.07 115.23 0 top
H9  HOLEA  [H_2P5]  15.07 35.36 270 top
H10  HOLEA  [H_2P5]  84.72 18.36 270 top
H11  HOLEA  [H_3P2N]  118.84 76.75 0 top
H12  HOLEA  [H_2P5]  181.37 29.86 270 top
H13  HOLEA  [H_2P5]  114.78 79.8 270 top
H14  HOLEA  [H_3P5X2P5N]  9.29 93.48 90 top
H15  HOLEA  [H_3P2]  172.37 70.96 0 top
J1  SHORT PADS  [SHORTPADS]  171.22 46.13 0 top
J2  SHORT PADS  [SHORTPADS]  159.54 56.74 180 bottom
J4  -  [JUMP_43X79]  180.85 13.11 180 top
J5  -  [JUMP_43X79]  178.02 7.55 90 top
JBAT1  SUYIN_125022HB008M200ZL  [SUYIN_125022HB008M200ZL_8P-T]  107.14 23.71 180 bottom
JDCIN1  SINGA_2DC3169-000111F  [SINGA_2DC3169-000111F_5P-T]  13.61 149.41 270 bottom
JDIMM1  DEREN_40-42271-26001RHF  [DEREN_40-42271-26001RHF_260P-T]  37.07 89.29 270 bottom
JEDP1  ACES_87242-3001-09  [ACES_87242-3001-09_30P]  22.87 143.51 0 bottom
JFAN1  ACES_50271-0040N-001  [ACES_50271-0040N-001_4P]  100.27 88.98 270 bottom
JHDD1  ACES_51530-01001-P01  [ACES_51530-01001-P01_10P]  179.88 18.31 270 bottom
JHDMI1  ACON_HMRA4-AK120C  [ACON_HMRA4-AK120C_19P]  10.55 100.03 90 bottom
JHDT1  SAMTE_ASP-136446-07-B  [SAMTE_ASP-136446-07-B_20P-T]  79.78 84.29 0 top
JHP1  SINGA_2SJ3095-140111F  [SINGA_2SJ3095-140111F_6P-T]  12.23 39.83 270 bottom
JKB1  JXT_FP257H-032S10M  [JXT_FP257H-032S10M_32P]  131.77 58.37 0 bottom
JLAN1  PS_601012-008041  [PS_601012-008041_8P]  12.92 129.77 270 top
JODD2  ACES_51530-01001-P01  [ACES_51530-01001-P01_10P]  184.08 54.2 270 bottom
JRTC1  ACES_50271-0020N-001  [ACES_50271-0020N-001_2P]  7.12 19.64 180 bottom
JSD1  DEREN_43-42095-01111RHF-R  [DEREN_43-42095-01111RHF-R_11P]  19.22 10.07 270 top
JSPK1  ACES_50278-00401-001  [ACES_50278-00401-001_4P]  41.77 7.63 0 top
JTP1  ACES_51522-00601-001  [ACES_51522-00601-001_6P]  175.52 18.32 180 bottom
JUSB1  ACON_TARAN-9R1391  [ACON_TARAN-9R1391_9P]  15.6 65.58 90 bottom
JUSB2  ACON_TARAN-9R1391  [ACON_TARAN-9R1391_9P]  15.6 85.88 90 bottom
JWLAN1  LOTES_APCI0128-P005A  [LOTES_APCI0128-P005A_75P]  163.12 37.43 0 bottom
L20  BLM15AX601SN1D_0402_2P  [MURAT_BLM15AX300SN1D_2P]  155.77 64.99 180 top
L21  BLM15AX601SN1D_0402_2P  [MURAT_BLM15AX300SN1D_2P]  158.65 63.07 270 top
L301  DLM0NSN900HY2D_4P  [MURAT_DLM0NSN900HY2D_4P]  21.92 56.74 180 bottom
L305  DLM0NSN900HY2D_4P  [MURAT_DLM0NSN900HY2D_4P]  22.43 84.35 180 bottom
L307  DLM0NSN900HY2D_4P  [MURAT_DLM0NSN900HY2D_4P]  23.56 149.76 270 top
L308  DLM0NSN900HY2D_4P  [MURAT_DLM0NSN900HY2D_4P]  30.74 10.11 180 top
LA5  0_0603_5%  [R0603_0OHM]  47.78 13.26 180 top
LA6  0_0603_5%  [R0603_0OHM]  47.78 10.03 180 top
LA7  0_0603_5%  [R0603_0OHM]  39.72 13.26 0 top
LA8  0_0603_5%  [R0603_0OHM]  39.72 10.03 0 top
LA9  BLM15PX221SN1D_2P  [MURAT_BLM15PX221SN1D_2P]  4.49 22.78 0 bottom
LED2  LTW-C193TS5-C_WHITE  [LED_LTW-C193TS5-C_2P]  3.37 2.6 180 bottom
LED3  LTW-C193TS5-C_WHITE  [LED_LTW-C193TS5-C_2P]  3.39 138.35 270 bottom
LED4  LTST-C191KFKT-2CA_ORANGE  [LED_LTST-C191KFKT-2CA_2P]  5.17 138.35 270 bottom
LH1  HCM1012GH900BP_4P  [INPAQ_HCM1012GH900BP_4P]  19.16 105.18 180 bottom
LH2  HCM1012GH900BP_4P  [INPAQ_HCM1012GH900BP_4P]  19.16 100.3 180 bottom
LH3  HCM1012GH900BP_4P  [INPAQ_HCM1012GH900BP_4P]  19.16 103.66 180 bottom
LH4  HCM1012GH900BP_4P  [INPAQ_HCM1012GH900BP_4P]  19.16 101.81 180 bottom
LV2  0_0402_5%  [R0402_0OHM]  102.39 135.04 270 top
LV3  0_0402_5%  [R0402_0OHM]  102.63 129.24 90 top
LV4  0_0402_5%  [R0402_0OHM]  104.36 131.78 90 bottom
LV6  0_0402_5%  [R0402_0OHM]  86.05 143.67 180 top
LV7  0_0402_5%  [R0402_0OHM]  81.89 148.56 180 top
LV8  0_0402_5%  [R0402_0OHM]  78.54 145.54 0 top
NOREF  -  []  2.37 35.36 90 top
NOREF#2  -  []  45.34 30.41 90 top
NOREF#3  -  []  76.67 155.36 0 top
NOREF#4  -  []  88.97 156.36 0 top
NOREF#5  -  []  121.03 53.82 90 top
NOREF#6  -  []  102.25 111.36 270 top
NOREF#7  -  []  3.98 155.66 90 top
NOREF#8  -  []  66.1 80.43 270 top
NOREF#9  -  []  84.72 18.36 90 top
NOREF#10  -  []  75.37 83.96 0 top
NOREF#11  -  []  123.8 3.47 0 top
NOREF#12  -  []  75.37 24.36 90 top
NOREF#13  -  []  181.37 29.86 270 top
NOREF#14  -  []  114.78 79.8 270 top
NOREF#15  -  []  107.47 159.86 0 top
NOREF#16  -  []  15.07 115.23 180 top
NOREF#17  -  []  74.96 -30.77 0 top
NOREF#18  -  []  3.98 143.16 90 top
NOREF#19  -  []  63.77 37.86 90 top
NOREF#20  -  []  10.12 144.62 0 top
NOREF#21  -  []  172.37 70.96 0 top
NOREF#22  -  []  63.63 41.69 90 bottom
NOREF#23  -  []  15.07 35.36 270 bottom
NOREF#24  -  []  181.37 29.86 90 bottom
NOREF#25  -  []  46.62 75.46 90 bottom
NOREF#26  -  []  45.41 39.84 90 bottom
NOREF#27  -  []  46.52 57.08 90 bottom
NOREF#28  -  []  45.53 32.38 180 bottom
NOREF#29  -  []  84.72 18.36 90 bottom
NOREF#30  -  []  102.57 103.12 180 bottom
PC101  1000P_0402_50V7K  [C_0402]  20.7 145.39 0 top
PC102  100P_0402_50V8J  [C_0402]  20.7 146.35 0 top
PC103  100P_0402_50V8J  [C_0402]  20.54 150.09 0 top
PC104  1000P_0402_50V7K  [C_0402]  20.54 149.14 0 top
PC201  1000P_0402_50V7K  [C_0402]  111.25 28.41 90 bottom
PC202  0.01U_0402_25V7K  [C_0402]  115.24 28.31 90 bottom
PC401  0.1U_0402_25V7K  [C_0402]  155.37 21.82 270 bottom
PC402  1000P_0402_50V7K  [C_0402]  162 23.72 0 top
PC403  0.1U_0402_25V6  [C_0402]  156.11 25.61 90 bottom
PC404  2200P_0402_50V7K  [C_0402]  155.22 25.61 90 bottom
PC405  10U_0805_25V6K  [C_0805]  153.89 25.47 90 bottom
PC407  22U_0603_6.3V6M  [C_0603]  155.03 12.67 90 top
PC408  22U_0603_6.3V6M  [C_0603]  155.03 12.67 90 bottom
PC409  22U_0603_6.3V6M  [C_0603]  161.44 11.9 0 top
PC410  22U_0603_6.3V6M  [C_0603]  161.44 11.9 0 bottom
PC411  4.7U_0603_6.3V6M  [C_0603]  160.33 21.66 270 top
PC412  680P_0402_50V7K  [C_0402]  158.27 20.73 90 top
PC413  1000P_0402_50V7K  [C_0402]  171.06 25.1 90 bottom
PC414  10U_0805_25V6K  [C_0805]  164.68 26.87 90 bottom
PC415  10U_0805_25V6K  [C_0805]  164.68 26.87 90 top
PC416  2200P_0402_50V7K  [C_0402]  166 27.65 0 bottom
PC417  0.1U_0402_25V6  [C_0402]  166 27.65 0 top
PC418  0.1U_0402_25V7K  [C_0402]  164.49 23.42 270 bottom
PC419  2.2U_0402_6.3V6M  [C_0402]  169.65 21.79 270 bottom
PC420  22U_0603_6.3V6M  [C_0603]  162.46 15.52 90 bottom
PC421  22U_0603_6.3V6M  [C_0603]  163.1 13.17 180 bottom
PC422  22U_0603_6.3V6M  [C_0603]  163.1 14.38 180 bottom
PC423  22U_0603_6.3V6M  [C_0603]  163.1 13.17 180 top
PC424  22U_0603_6.3V6M  [C_0603]  163.1 14.38 180 top
PC425  22U_0603_6.3V6M  [C_0603]  169.19 14.38 0 top
PC426  680P_0402_50V7K  [C_0402]  166.4 22.32 0 top
PC427  4.7U_0603_6.3V6M  [C_0603]  169.45 23.39 180 top
PC428  4.7U_0402_6.3V6M  [C_0402]  162 25.43 0 top
PC429  1U_0201_6.3V6M  [C_0201]  160.49 27.01 90 top
PC451  1000P_0402_50V7K  [C_0402]  165.65 32.16 180 top
PC501  0.1U_0402_25V6  [C_0402]  40.78 102.33 0 bottom
PC502  2200P_0402_50V7K  [C_0402]  40.78 102.33 0 top
PC503  10U_0805_25V6K  [C_0805]  41.24 103.45 90 bottom
PC504  10U_0805_25V6K  [C_0805]  41.24 103.45 90 top
PC505  0.1U_0402_25V7K  [C_0402]  39.59 111.17 90 bottom
PC506  10U_0603_6.3V6M  [C_0603]  31.84 112.87 90 bottom
PC507  10U_0603_6.3V6M  [C_0603]  33.05 112.87 90 bottom
PC508  1U_0402_10V6K  [C_0402]  40.74 115.22 180 top
PC509  22U_0603_6.3V6M  [C_0603]  29.75 103.85 180 bottom
PC510  22U_0603_6.3V6M  [C_0603]  29.75 105.12 180 bottom
PC511  22U_0603_6.3V6M  [C_0603]  29.75 107.66 180 bottom
PC512  22U_0603_6.3V6M  [C_0603]  29.75 106.39 180 bottom
PC513  22U_0603_6.3V6M  [C_0603]  29.75 108.93 180 bottom
PC514  22U_0603_6.3V6M  [C_0603]  29.75 110.2 180 bottom
PC515  0.033U_0402_16V7K  [C_0402]  32.62 115.73 180 bottom
PC516  1U_0402_10V6K  [C_0402]  39.83 115.22 0 bottom
PC517  680P_0402_50V7K  [C_0402]  40.67 111.04 270 top
PC518  0.1U_0402_10V7K  [C_0402]  36.98 117 270 top
PC519  0.1U_0402_10V7K  [C_0402]  36.1 117 270 top
PC601  0.1U_0402_25V6  [C_0402]  64.1 20.15 90 bottom
PC602  680P_0402_50V7K  [C_0402]  72.1 19.59 0 bottom
PC603  0.1U_0402_25V7K  [C_0402]  70.64 16.06 270 top
PC604  2200P_0402_50V7K  [C_0402]  68.86 19.19 90 top
PC605  0.1U_0402_25V6  [C_0402]  71.53 19.19 90 top
PC606  10U_0805_25V6K  [C_0805]  70.2 19.14 90 top
PC608  330P_0402_50V7K  [C_0402]  61.37 16.25 90 top
PC609  22U_0603_6.3V6M  [C_0603]  65.62 22.45 180 bottom
PC610  22U_0603_6.3V6M  [C_0603]  65.62 23.72 180 bottom
PC611  22U_0603_6.3V6M  [C_0603]  65.62 22.45 180 top
PC612  22U_0603_6.3V6M  [C_0603]  65.62 23.72 180 top
PC613  2.2U_0402_6.3V6M  [C_0402]  65.32 14.13 180 top
PC614  1U_0402_6.3V6K  [C_0402]  63.08 15.03 270 top
PC705  2200P_0402_25V7K  [C_0402]  138.18 20.31 270 bottom
PC708  0.1U_0402_25V6  [C_0402]  146.38 13.04 0 bottom
PC715  2200P_0402_50V7K  [C_0402]  150.83 20.57 0 bottom
PC721  0.22U_0603_25V7K  [C_0603]  143.7 19.61 270 bottom
PC747  0.1U_0402_25V6  [C_0402]  150 20.58 180 bottom
PC748  0.1U_0402_25V6  [C_0402]  160.94 65.17 90 top
PC750  0.22U_0603_25V7K  [C_0603]  146.78 21.13 0 bottom
PC751  560P_0402_50V7K  [C_0402]  152.45 13.42 0 bottom
PC752  0.015U_0402_25V7K  [C_0402]  152.45 12.53 0 bottom
PC757  1U_0603_25V6K  [C_0603]  143.75 14.14 90 bottom
PC760  10U_0805_25V6K  [C_0805]  142.14 20.11 270 bottom
PC761  10U_0805_25V6K  [C_0805]  120.78 21.18 0 bottom
PC762  10U_0805_25V6K  [C_0805]  140.41 20.13 270 bottom
PC765  0.1U_0402_25V7K  [C_0402]  139.09 20.31 270 bottom
PC767  680P_0402_50V7K  [C_0402]  137.44 11.9 90 bottom
PC768  1U_0402_16V6K  [C_0402]  142.71 16.44 180 bottom
PC769  1U_0402_16V6K  [C_0402]  142.7 17.37 180 bottom
PC775  10U_0805_25V6K  [C_0805]  120.78 19.4 0 bottom
PC776  10U_0805_25V6K  [C_0805]  120.78 17.62 0 bottom
PC779  0.1U_0402_25V7K  [C_0402]  123.71 19.78 0 bottom
PC801  2.2U_0402_10V6M  [C_0402]  149.19 42.59 270 bottom
PC802  10U_0805_25V6K  [C_0805]  153.32 54.87 90 bottom
PC803  10U_0805_25V6K  [C_0805]  153.32 54.87 90 top
PC804  0.1U_0402_25V7K  [C_0402]  149.52 44.58 270 bottom
PC805  0.47U_0402_25V6K  [C_0402]  156.1 47.97 0 bottom
PC806  680P_0402_50V7K  [C_0402]  139.79 43.01 90 bottom
PC807  0.1U_0402_25V6  [C_0402]  157.89 47.96 90 bottom
PC808  0.1U_0402_25V6  [C_0402]  152.94 40.09 90 top
PC809  82P_0402_50V8J  [C_0402]  153.88 40.16 0 top
PC810  330P_0402_50V8J  [C_0402]  154.26 37.5 0 top
PC811  1000P_0402_25V8J  [C_0402]  152.75 37.86 90 bottom
PC812  330P_0402_50V8J  [C_0402]  155.16 48.75 270 top
PC813  82P_0402_50V8J  [C_0402]  154.22 48.67 180 top
PC814  0.1U_0402_25V6  [C_0402]  156.1 37.5 0 top
PC815  0.1U_0402_25V6  [C_0402]  154.32 35.78 0 top
PC816  0.1U_0402_25V6  [C_0402]  155.79 40.09 90 top
PC817  0.1U_0402_25V6  [C_0402]  157.83 48.75 270 top
PC818  0.1U_0402_25V6  [C_0402]  154.97 47.96 180 bottom
PC819  10P_0402_50V8J  [C_0402]  158.33 37.93 90 bottom
PC822  2.2U_0402_10V6M  [C_0402]  157.71 41.88 180 top
PC823  10U_0805_25V6K  [C_0805]  141.23 25.05 0 bottom
PC824  10U_0805_25V6K  [C_0805]  141.23 25.05 0 top
PC825  0.1U_0402_25V7K  [C_0402]  148.91 40.81 0 bottom
PC826  0.47U_0402_25V6K  [C_0402]  154.13 38.38 0 bottom
PC827  680P_0402_50V7K  [C_0402]  129.83 33.62 180 bottom
PC828  0.1U_0402_25V6  [C_0402]  154.4 36.62 270 bottom
PC831  0.1U_0402_25V6  [C_0402]  153.13 51.61 270 top
PC832  2200P_0402_50V7K  [C_0402]  153.13 51.61 270 bottom
PC833  0.47U_0402_6.3V6K  [C_0402]  156.87 42.82 90 top
PC834  100P_0402_25V8K  [C_0402]  155.29 36.62 270 bottom
PC835  100P_0402_25V8K  [C_0402]  159.34 46.07 0 bottom
PC836  10P_0402_50V8J  [C_0402]  92.23 72.24 270 bottom
PC837  10P_0402_50V8J  [C_0402]  92.24 77.63 180 bottom
PC901  0.1U_0402_25V7K  [C_0402]  45.41 150.91 0 top
PC902  0.22U_0402_10V6K  [C_0402]  41.57 144.43 180 top
PC903  680P_0402_50V7K  [C_0402]  41.49 144.62 90 bottom
PC904  2200P_0402_50V7K  [C_0402]  42.49 148.87 180 top
PC905  0.1U_0402_25V6  [C_0402]  41.7 151.54 180 top
PC906  10U_0805_25V6K  [C_0805]  42.03 150.21 180 top
PC907  330P_0402_50V7K  [C_0402]  45.7 142.21 180 top
PC908  22U_0603_6.3V6M  [C_0603]  47.08 156.3 90 top
PC909  22U_0603_6.3V6M  [C_0603]  45.81 156.3 90 top
PC910  22U_0603_6.3V6M  [C_0603]  45.81 156.3 90 bottom
PC911  22U_0603_6.3V6M  [C_0603]  47.08 156.3 90 bottom
PC912  2.2U_0402_6.3V6M  [C_0402]  47.37 145.2 270 top
PC913  1U_0402_6.3V6K  [C_0402]  47.37 143.17 270 top
PC943  2200P_0402_50V7K  [C_0402]  141.37 27.34 0 bottom
PC944  0.1U_0402_25V6  [C_0402]  141.37 26.38 0 bottom
PC986  0.1U_0402_25V6  [C_0402]  155.29 45.42 90 top
PC987  0.1U_0402_25V6  [C_0402]  153.25 46.33 270 top
PC988  0.1U_0402_25V6  [C_0402]  156.17 46.33 270 top
PC1001  0.1U_0402_25V6  [C_0402]  88.66 140.49 0 top
PC1002  1U_0402_6.3V6K  [C_0402]  55.92 111.52 90 bottom
PC1003  0.1U_0402_25V6  [C_0402]  58.89 101.71 270 top
PC1004  2.2U_0402_6.3V6M  [C_0402]  91.38 130.37 270 top
PC1005  1U_0402_6.3V6K  [C_0402]  93.31 138.46 180 top
PC1006  0.1U_0402_25V6  [C_0402]  58.07 104.41 90 top
PC1007  2.2U_0402_6.3V6M  [C_0402]  85.72 133.4 180 top
PC1008  0.47U_0402_6.3V6K  [C_0402]  50.46 108.62 180 bottom
PC1009  2.2U_0402_6.3V6M  [C_0402]  89.82 136.21 0 top
PC1010  0.22U_0402_10V6K  [C_0402]  59.71 105.63 0 bottom
PC1011  0.1U_0402_25V6  [C_0402]  58.07 103.48 270 top
PC1012  1U_0402_6.3V6K  [C_0402]  89.69 141.38 90 top
PC1013  10P_0402_50V8J  [C_0402]  54.19 114.6 270 bottom
PC1014  10P_0402_50V8J  [C_0402]  53.3 114.6 270 bottom
PC1015  2.2U_0402_6.3V6M  [C_0402]  85.56 132.19 180 top
PC1016  0.1U_0402_25V6  [C_0402]  58.38 103.68 270 bottom
PC1017  1U_0402_6.3V6K  [C_0402]  92.55 134.71 180 top
PC1018  0.1U_0402_25V6  [C_0402]  88.66 139.6 0 top
PC1019  2.2U_0402_6.3V6M  [C_0402]  88.99 135.41 180 top
PC1020  0.1U_0402_25V6  [C_0402]  53.49 103.61 270 bottom
PC1021  2200P_0402_50V7K  [C_0402]  63.99 111.54 180 top
PC1022  2.2U_0402_6.3V6M  [C_0402]  89.82 135.32 0 top
PC1023  2.2U_0402_6.3V6M  [C_0402]  89.59 131.56 180 top
PC1024  68P_0402_50V8J  [C_0402]  56.4 103.6 0 bottom
PC1025  2.2U_0402_6.3V6M  [C_0402]  89.59 132.45 180 top
PC1026  330P_0402_50V8J  [C_0402]  56.4 101.88 0 bottom
PC1027  1U_0402_6.3V6K  [C_0402]  92.23 133.51 180 top
PC1028  2.2U_0402_6.3V6M  [C_0402]  86.85 132.45 0 top
PC1029  0.1U_0402_25V6  [C_0402]  59.84 100.79 90 top
PC1030  2.2U_0402_6.3V6M  [C_0402]  86.85 131.56 0 top
PC1031  2.2U_0402_6.3V6M  [C_0402]  86.81 133.38 0 top
PC1032  10P_0402_50V8J  [C_0402]  55.08 114.6 270 bottom
PC1033  2.2U_0402_6.3V6M  [C_0402]  86.79 134.36 0 top
PC1034  0.1U_0402_25V6  [C_0402]  63.99 111.54 180 bottom
PC1035  2.2U_0402_6.3V6M  [C_0402]  85.7 134.31 180 top
PC1036  0.47U_0402_25V6K  [C_0402]  55.29 103.6 180 bottom
PC1037  2.2U_0402_6.3V6M  [C_0402]  89.88 137.57 0 top
PC1038  2.2U_0402_6.3V6M  [C_0402]  88.99 137.19 180 top
PC1039  0.1U_0402_25V6  [C_0402]  89.88 138.5 0 top
PC1040  2.2U_0402_6.3V6M  [C_0402]  88.99 136.3 180 top
PC1041  10U_0603_6.3V6M  [C_0603]  81.31 115.66 90 top
PC1042  680P_0402_50V7K  [C_0402]  68.8 103.22 180 bottom
PC1043  2.2U_0603_10V6K  [C_0603]  59.65 107.98 0 bottom
PC1044  0.22U_0603_25V7K  [C_0603]  59.74 111.05 270 bottom
PC1045  10U_0603_6.3V6M  [C_0603]  90.38 133.8 180 top
PC1046  10U_0603_6.3V6M  [C_0603]  82.58 115.66 90 top
PC1047  2.2U_0603_10V6K  [C_0603]  52.07 109.69 180 bottom
PC1048  10U_0805_25V6K  [C_0805]  66.8 111.92 0 top
PC1049  10U_0805_25V6K  [C_0805]  66.8 111.92 0 bottom
PC1050  10U_0603_6.3V6M  [C_0603]  79.34 115.16 90 top
PC1051  10U_0603_6.3V6M  [C_0603]  78.07 115.16 90 top
PC1052  10U_0603_6.3V6M  [C_0603]  90.48 131.86 0 top
PC1053  10U_0603_6.3V6M  [C_0603]  93.44 137 180 top
PC1054  330U_2V_M  [C_5X4P5]  71.91 111.79 270 bottom
PC1055  330U_2V_M  [C_5X4P5]  77.69 111.79 270 bottom
PC1056  330U_2V_M  [C_5X4P5]  79.66 102.84 90 bottom
PC2001  0.1U_0402_25V6  [C_0402]  52.1 8.74 270 top
PC2002  0.1U_0402_16V7K  [C_0402]  73.94 7.16 270 top
PC2003  1U_0402_6.3V6K  [C_0402]  73.13 11.46 180 top
PC2004  0.01U_0402_25V7K  [C_0402]  64.42 8.03 270 top
PC2005  0.01U_0402_25V7K  [C_0402]  52.94 17.11 180 top
PC2006  1U_0402_6.3V6K  [C_0402]  55.78 9.6 90 top
PC2007  22U_0603_6.3V6M  [C_0603]  65.12 9.17 90 top
PC2008  4.7U_0603_6.3V6K  [C_0603]  53.22 8.11 0 top
PC2009  4.7U_0603_6.3V6K  [C_0603]  74.2 9.49 270 top
PC2010  22U_0603_6.3V6M  [C_0603]  53.88 17.43 0 top
PC9001  22U_0603_6.3V6M  [C_0603]  90.43 59.53 270 top
PC9002  22U_0603_6.3V6M  [C_0603]  92.9 58.02 180 top
PC9003  22U_0603_6.3V6M  [C_0603]  93.92 58.02 0 top
PC9004  22U_0603_6.3V6M  [C_0603]  92.36 56.05 180 top
PC9005  22U_0603_6.3V6M  [C_0603]  93.98 56.05 0 top
PC9006  22U_0603_6.3V6M  [C_0603]  92.33 53.79 180 top
PC9007  22U_0603_6.3V6M  [C_0603]  131.47 53.88 0 top
PC9008  22U_0603_6.3V6M  [C_0603]  127.51 48.21 225 top
PC9009  22U_0603_6.3V6M  [C_0603]  125.69 50 225 bottom
PC9010  22U_0603_6.3V6M  [C_0603]  124.81 50.89 225 bottom
PC9011  22U_0603_6.3V6M  [C_0603]  101.45 63.97 180 top
PC9012  22U_0603_6.3V6M  [C_0603]  100.79 61.95 180 top
PC9013  22U_0603_6.3V6M  [C_0603]  100.54 58.95 90 top
PC9014  22U_0603_6.3V6M  [C_0603]  98.36 59.98 180 top
PC9015  22U_0603_6.3V6M  [C_0603]  100.22 53.23 270 top
PC9016  22U_0603_6.3V6M  [C_0603]  100.07 56.24 0 top
PC9017  22U_0603_6.3V6M  [C_0603]  101.48 57.84 180 top
PC9018  22U_0603_6.3V6M  [C_0603]  92.41 52.1 180 top
PC9019  22U_0603_6.3V6M  [C_0603]  93.86 52.16 0 top
PC9020  22U_0603_6.3V6M  [C_0603]  96.97 52.14 0 top
